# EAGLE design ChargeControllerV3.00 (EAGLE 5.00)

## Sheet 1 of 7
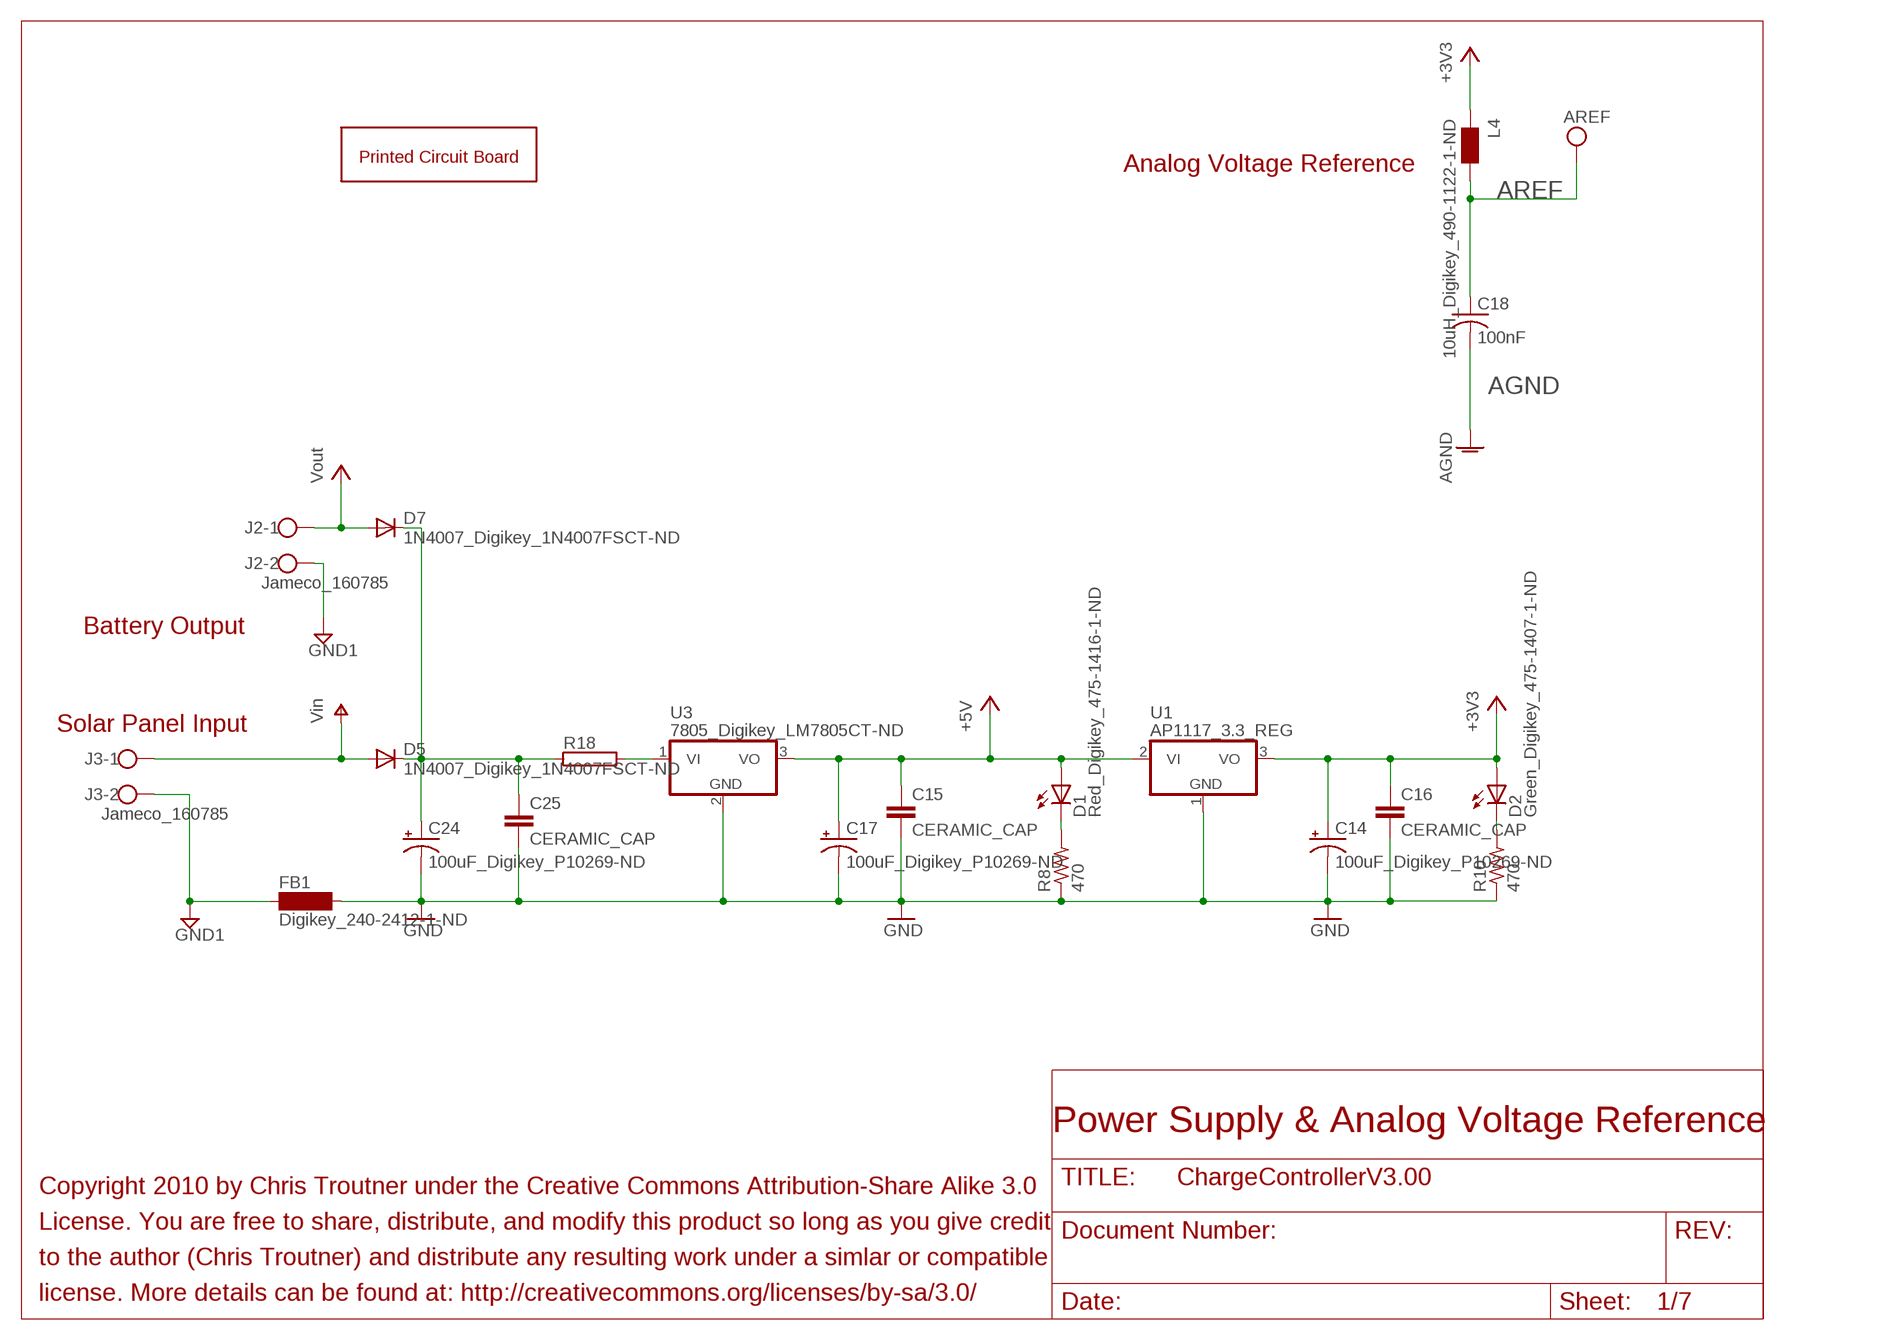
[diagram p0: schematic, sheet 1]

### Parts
C14  100uF_Digikey_P10269-ND  CPOL-USE2.5-7  [E2,5-7]
C15  CERAMIC_CAP  [C1206]
C16  CERAMIC_CAP  [C1206]
C17  100uF_Digikey_P10269-ND  CPOL-USE2.5-7  [E2,5-7]
C18  100nF  C-USC1206K  [C1206K]
C24  100uF_Digikey_P10269-ND  CPOL-USE2.5-7  [E2,5-7]
C25  CERAMIC_CAP  [C1206]
D1  Red_Digikey_475-1416-1-ND  LED_1206  [CHIPLED_1206]
D2  Green_Digikey_475-1407-1-ND  LED_1206  [CHIPLED_1206]
D5  1N4007_Digikey_1N4007FSCT-ND  1N4004  [DO41-10]
D7  1N4007_Digikey_1N4007FSCT-ND  1N4004  [DO41-10]
FB1  Digikey_240-2412-1-ND  SM-1206  [SM-1206]
J2  Jameco_160785  W237-102  [W237-102]
J3  Jameco_160785  W237-102  [W237-102]
L4  10uH_Digikey_490-1122-1-ND  WE-MK_0805  [0805]
R8  470  RESISTOR_1206  [C1206]
R10  470  RESISTOR_1206  [C1206]
R18  RMPC70-2  [MPC70-2]
U1  AP1117_3.3_REG  [TO252]
U3  7805_Digikey_LM7805CT-ND  7805T  [TO220H]
U$1  PCB_RM2015S  [PCB_RM2015S]

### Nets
+3V3: C14.+ C16.1 D2.A L4.1 U1.3(VO) ; also sheet 6
+5V: C15.1 C17.+ D1.A U1.2(VI) U3.3(VO) ; also sheet 2,3,4,5,6
AGND: C18.2 ; also sheet 5
AREF: C18.1 L4.2
GND: C14.- C15.2 C16.2 C17.- C24.- C25.2 FB1.2 R8.1 R10.1 U1.1(GND) U3.2(GND) ; also sheet 2,3,4,5,6
GND1: FB1.1 J2.2 J3.2 ; also sheet 2
N$1: C24.+ C25.1 D5.C D7.C R18.1
N$3: R18.2 U3.1(VI)
N$5: D1.C R8.2
N$6: D2.C R10.2
N$35: D7.A J2.1 ; supply symbol labelled Vout ; also sheet 2,3
VIN: D5.A J3.1 ; supply symbol labelled Vin ; also sheet 2,3

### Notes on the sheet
- Analog Voltage Reference
- Battery Output
- Solar Panel Input
- Power Supply & Analog Voltage Reference
- Copyright 2010 by Chris Troutner under the Creative Commons Attribution-Share Alike 3.0
- License. You are free to share, distribute, and modify this product so long as you give credit
- to the author (Chris Troutner) and distribute any resulting work under a simlar or compatible
- license. More details can be found at: http://creativecommons.org/licenses/by-sa/3.0/

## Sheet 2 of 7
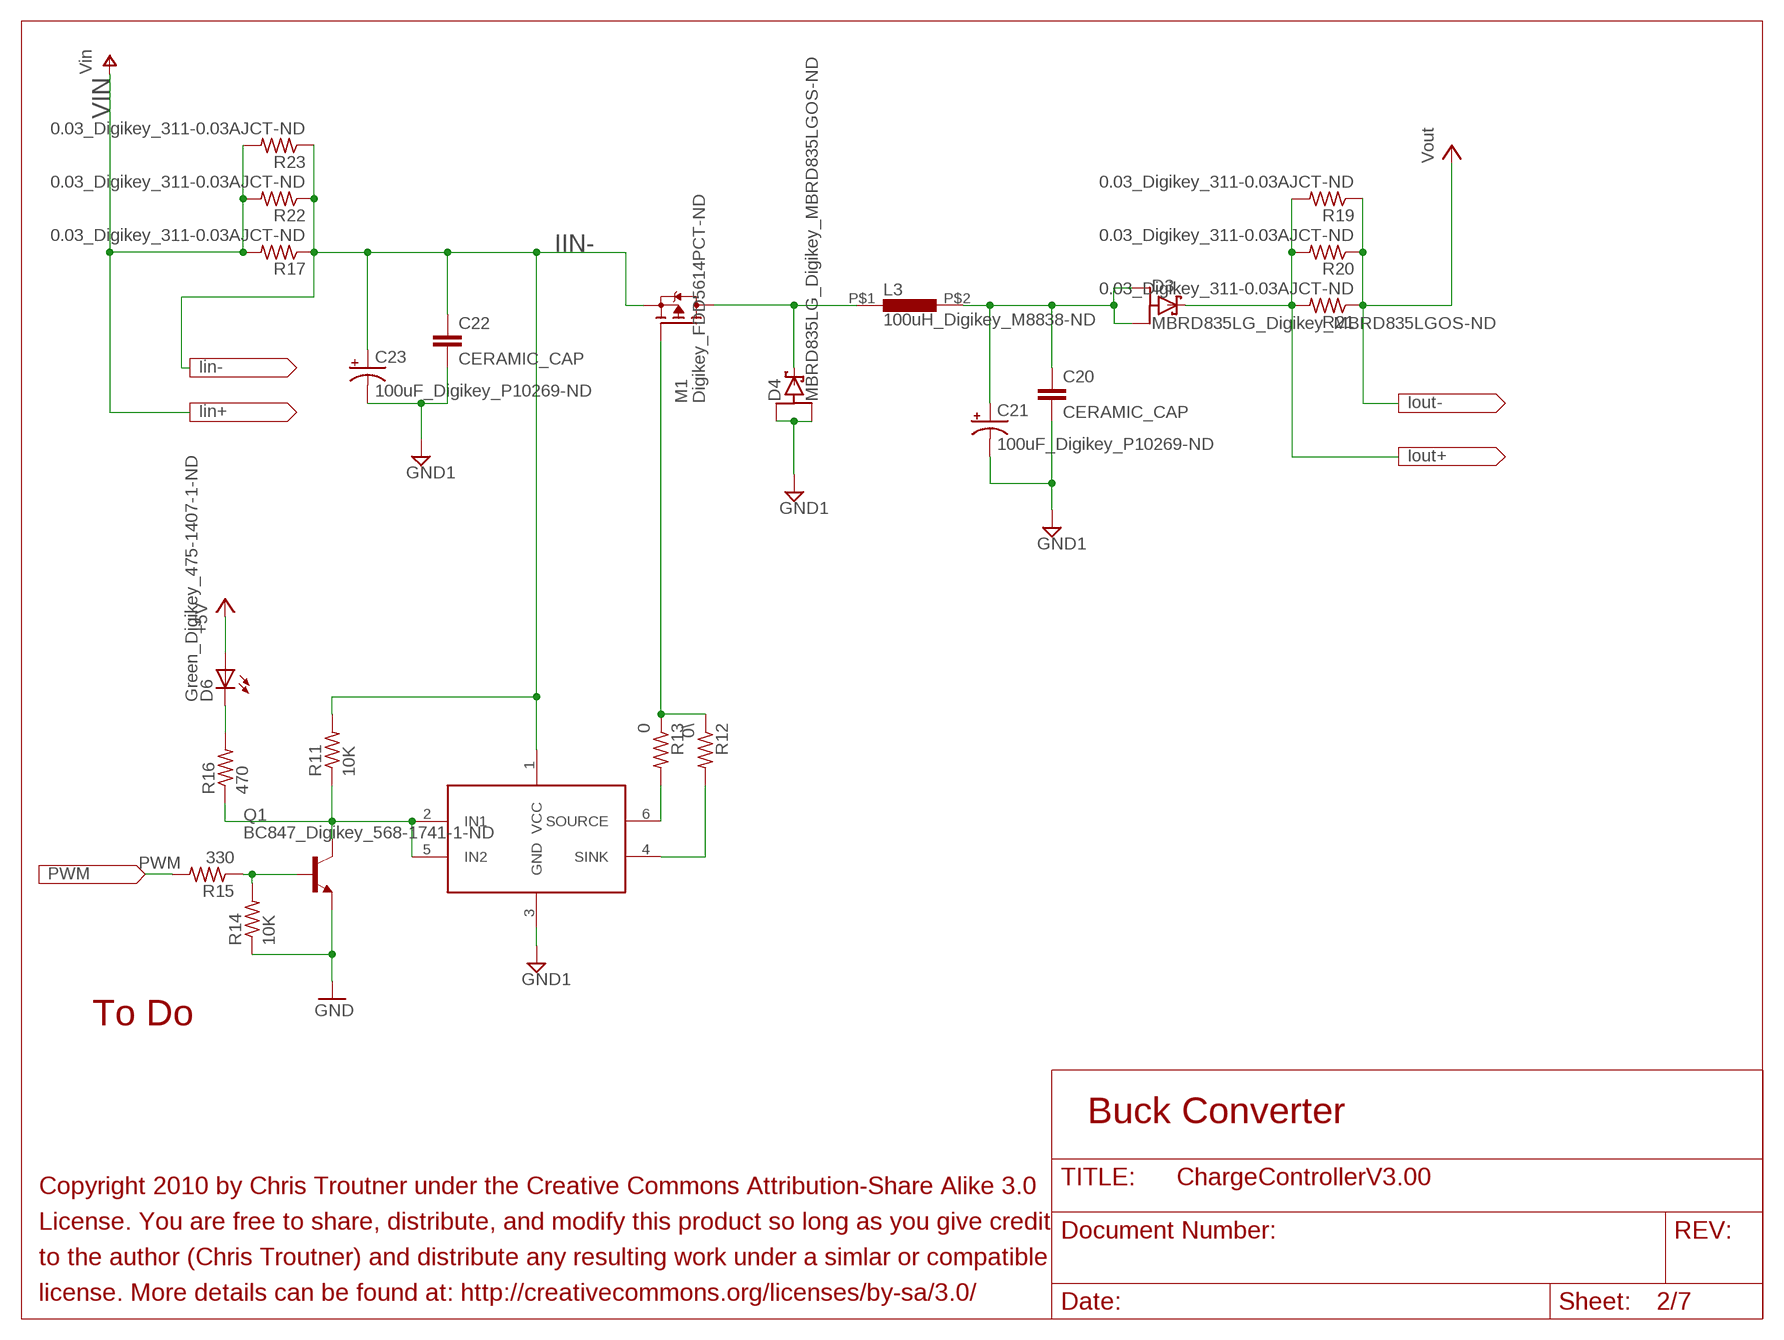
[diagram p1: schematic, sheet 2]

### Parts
C20  CERAMIC_CAP  [C1206]
C21  100uF_Digikey_P10269-ND  CPOL-USE2.5-7  [E2,5-7]
C22  CERAMIC_CAP  [C1206]
C23  100uF_Digikey_P10269-ND  CPOL-USE2.5-7  [E2,5-7]
D3  MBRD835LG_Digikey_MBRD835LGOS-ND  DIODE_SCHOTTKY_MBRD835LG  [DPAK_TO252]
D4  MBRD835LG_Digikey_MBRD835LGOS-ND  DIODE_SCHOTTKY_MBRD835LG  [DPAK_TO252]
D6  Green_Digikey_475-1407-1-ND  LEDCHIPLED_1206  [CHIPLED_1206]
L3  100uH_Digikey_M8838-ND  2312-RC  [2312-RC]
M1  Digikey_FDD5614PCT-ND  SPD30P06PTO252  [TO252]
Q1  BC847_Digikey_568-1741-1-ND  BC849SMD  [SOT23-BEC]
R11  10K  RESISTOR_1206  [C1206]
R12  0\  RESISTOR_1206  [C1206]
R13  0  RESISTOR_1206  [C1206]
R14  10K  RESISTOR_1206  [C1206]
R15  330  RESISTOR_1206  [C1206]
R16  470  RESISTOR_1206  [C1206]
R17  0.03_Digikey_311-0.03AJCT-ND  RESISTOR_1206  [C1206]
R19  0.03_Digikey_311-0.03AJCT-ND  RESISTOR_1206  [C1206]
R20  0.03_Digikey_311-0.03AJCT-ND  RESISTOR_1206  [C1206]
R21  0.03_Digikey_311-0.03AJCT-ND  RESISTOR_1206  [C1206]
R22  0.03_Digikey_311-0.03AJCT-ND  RESISTOR_1206  [C1206]
R23  0.03_Digikey_311-0.03AJCT-ND  RESISTOR_1206  [C1206]
U2  ZXGD3003  [SOT23-6]

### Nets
+5V: D6.A ; also sheet 1,3,4,5,6
GND: Q1.E R14.1 ; also sheet 1,3,4,5,6
GND1: C20.2 C21.- C22.2 C23.- D4.1(A) D4.3(A1) U2.3(GND) ; also sheet 1
IIN-: C22.1 C23.+ M1.2(S) R11.2 R17.1 R22.1 R23.1 U2.1(VCC) ; also sheet 3
IOUT+: D3.4(C) R19.2 R20.2 R21.2 ; also sheet 3
N$8: R13.2 U2.6(SOURCE)
N$9: D6.C R16.2
N$10: Q1.B R14.2 R15.1
N$16: R12.2 U2.4(SINK)
N$21: M1.1(G) R12.1 R13.1
N$24: Q1.C R11.1 R16.1 U2.2(IN1) U2.5(IN2)
N$30: D4.4(C) L3.P$1 M1.3(D)
N$34: C20.1 C21.+ D3.1(A) D3.3(A1) L3.P$2
N$35: R19.1 R20.1 R21.1 ; supply symbol labelled Vout ; also sheet 1,3
PWM: R15.2 ; also sheet 5
VIN: R17.2 R22.2 R23.2 ; supply symbol labelled Vin ; also sheet 1,3

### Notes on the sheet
- To Do
- Buck Converter
- Copyright 2010 by Chris Troutner under the Creative Commons Attribution-Share Alike 3.0
- License. You are free to share, distribute, and modify this product so long as you give credit
- to the author (Chris Troutner) and distribute any resulting work under a simlar or compatible
- license. More details can be found at: http://creativecommons.org/licenses/by-sa/3.0/

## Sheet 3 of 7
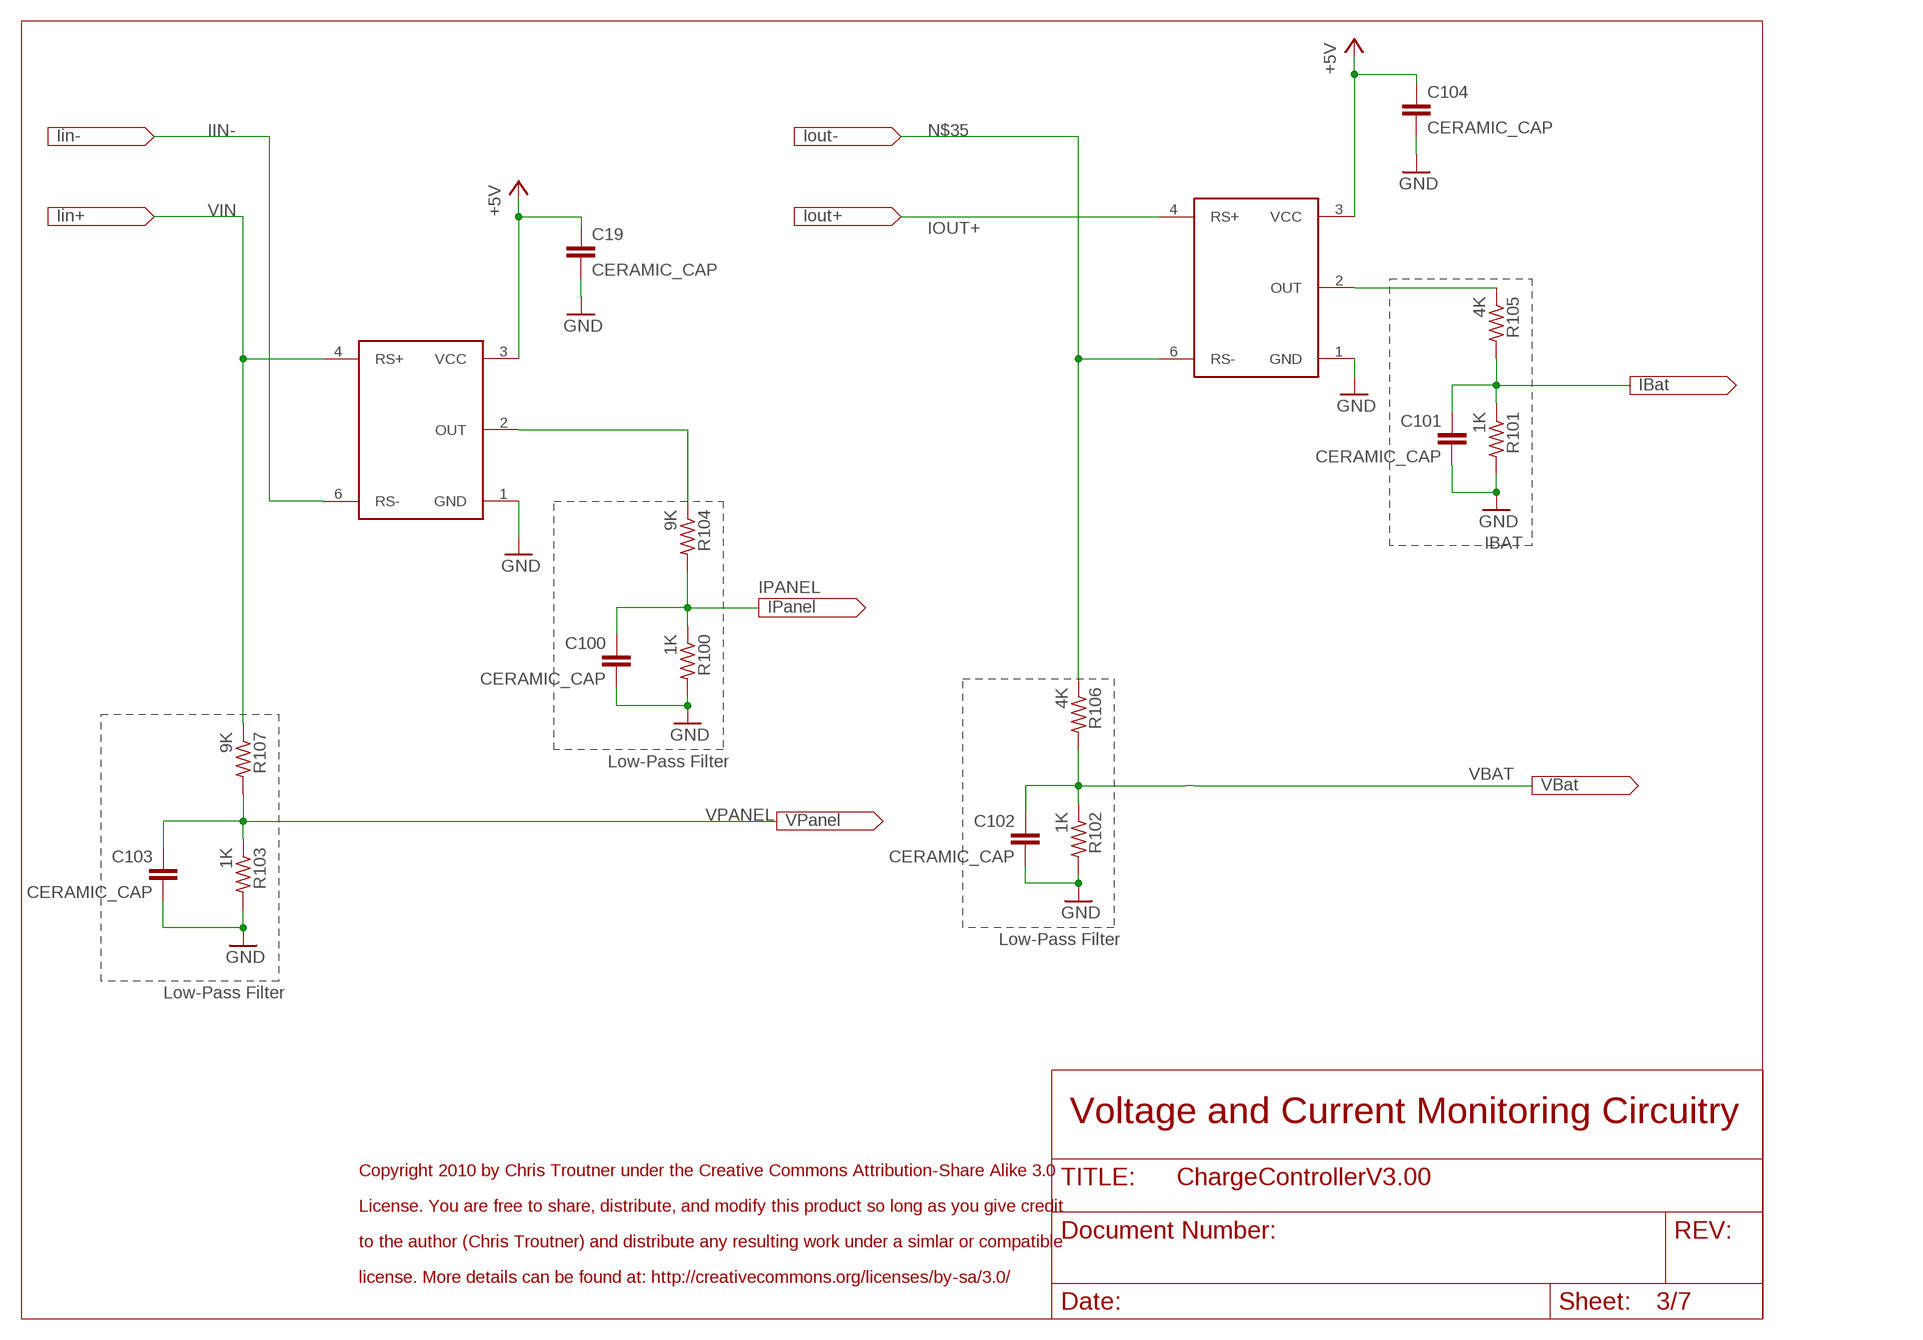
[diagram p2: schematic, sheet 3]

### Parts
C19  CERAMIC_CAP  [C1206]
C100  CERAMIC_CAP  [C1206]
C101  CERAMIC_CAP  [C1206]
C102  CERAMIC_CAP  [C1206]
C103  CERAMIC_CAP  [C1206]
C104  CERAMIC_CAP  [C1206]
IC3  MAX4372_CURRENT  [SOT23-6]
IC4  MAX4372_CURRENT  [SOT23-6]
R100  1K  RESISTOR_1206  [C1206]
R101  1K  RESISTOR_1206  [C1206]
R102  1K  RESISTOR_1206  [C1206]
R103  1K  RESISTOR_1206  [C1206]
R104  9K  RESISTOR_1206  [C1206]
R105  4K  RESISTOR_1206  [C1206]
R106  4K  RESISTOR_1206  [C1206]
R107  9K  RESISTOR_1206  [C1206]

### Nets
+5V: C19.1 C104.1 IC3.3(VCC) IC4.3(VCC) ; also sheet 1,2,4,5,6
GND: C19.2 C100.2 C101.2 C102.2 C103.2 C104.2 IC3.1(GND) IC4.1(GND) R100.2 R101.2 R102.2 R103.2 ; also sheet 1,2,4,5,6
IBAT: C101.1 R101.1 R105.2 ; also sheet 5
IIN-: IC3.6(RS-) ; also sheet 2
IOUT+: IC4.4(RS+) ; also sheet 2
IPANEL: C100.1 R100.1 R104.2 ; also sheet 5
N$12: IC4.2(OUT) R105.1
N$14: IC3.2(OUT) R104.1
N$35: IC4.6(RS-) R106.1 ; also sheet 1,2
VBAT: C102.1 R102.1 R106.2 ; also sheet 5
VIN: IC3.4(RS+) R107.1 ; also sheet 1,2
VPANEL: C103.1 R103.1 R107.2 ; also sheet 5

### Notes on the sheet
- Low-Pass Filter
- Low-Pass Filter
- Low-Pass Filter
- Voltage and Current Monitoring Circuitry
- Copyright 2010 by Chris Troutner under the Creative Commons Attribution-Share Alike 3.0
- License. You are free to share, distribute, and modify this product so long as you give credit
- to the author (Chris Troutner) and distribute any resulting work under a simlar or compatible
- license. More details can be found at: http://creativecommons.org/licenses/by-sa/3.0/

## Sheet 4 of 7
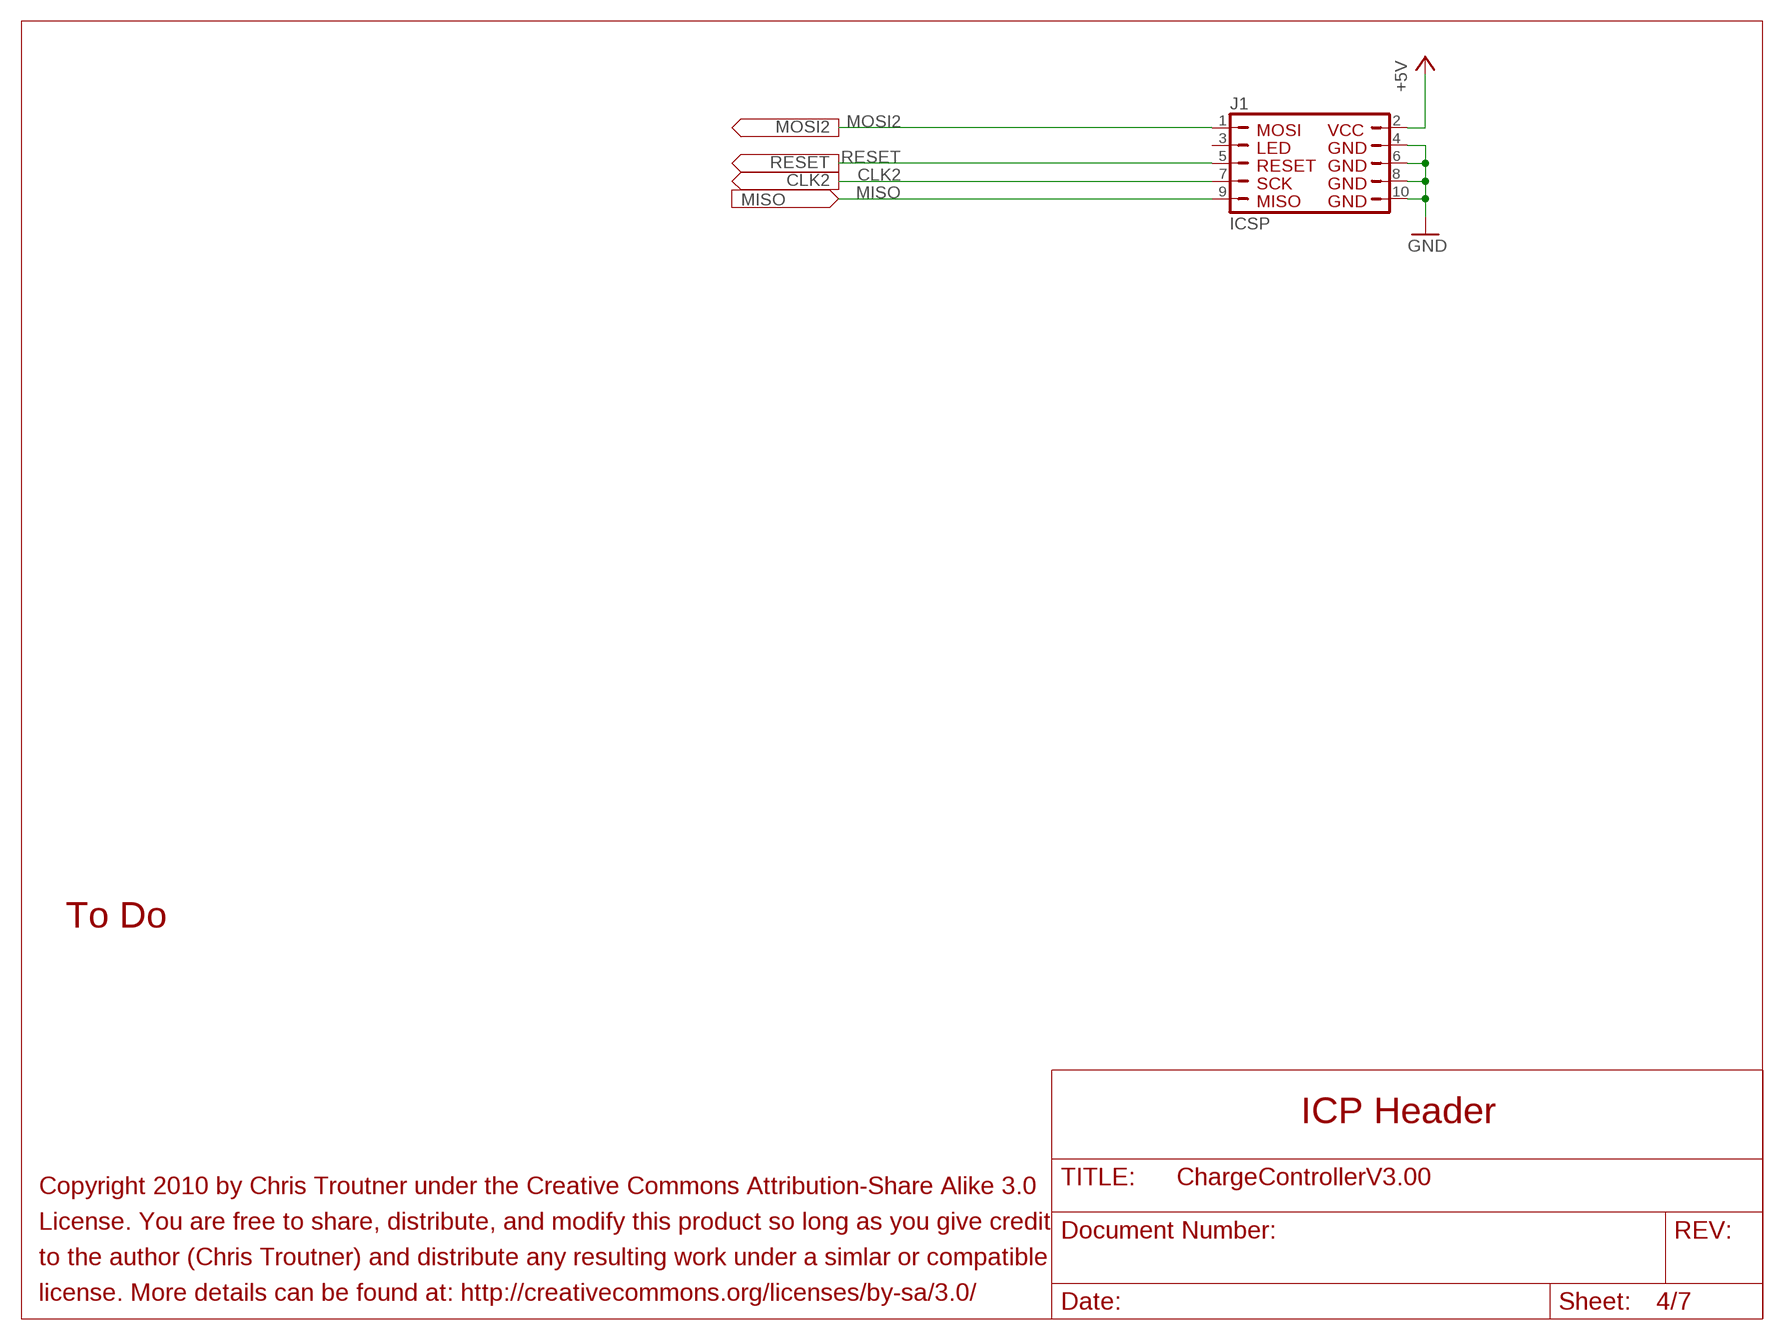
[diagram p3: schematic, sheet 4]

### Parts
J1  ICSP  [ICSP]

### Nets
+5V: J1.2 ; also sheet 1,2,3,5,6
CLK2: J1.7 ; also sheet 5,6
GND: J1.4 J1.6 J1.8 J1.10 ; also sheet 1,2,3,5,6
MISO: J1.9 ; also sheet 5,6
MOSI2: J1.1 ; also sheet 5,6
RESET: J1.5 ; also sheet 5
Unconnected: J1.3

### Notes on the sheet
- To Do
- ICP Header
- Copyright 2010 by Chris Troutner under the Creative Commons Attribution-Share Alike 3.0
- License. You are free to share, distribute, and modify this product so long as you give credit
- to the author (Chris Troutner) and distribute any resulting work under a simlar or compatible
- license. More details can be found at: http://creativecommons.org/licenses/by-sa/3.0/

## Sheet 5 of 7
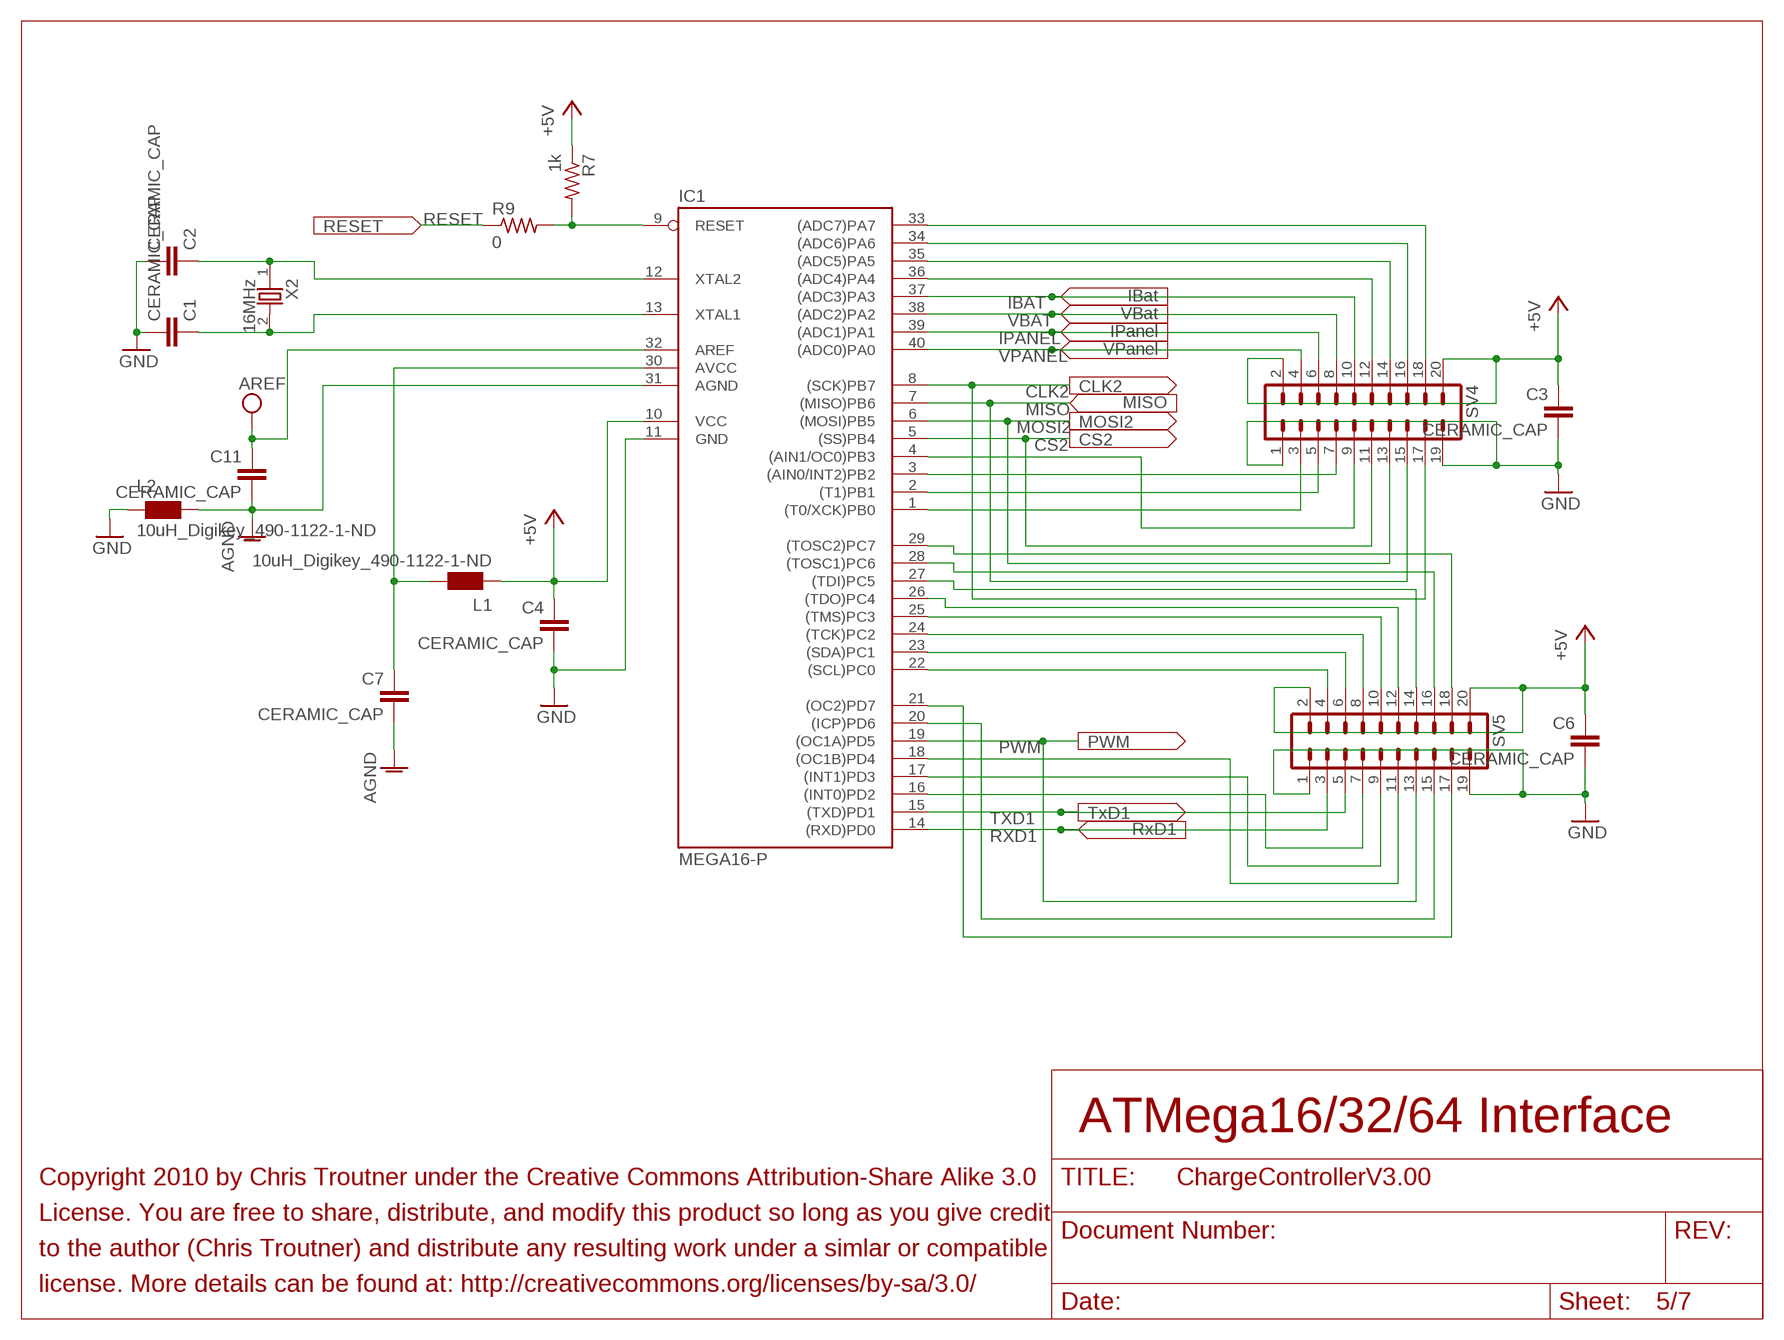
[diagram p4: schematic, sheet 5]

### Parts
C1  CERAMIC_CAP  [C1206]
C2  CERAMIC_CAP  [C1206]
C3  CERAMIC_CAP  [C1206]
C4  CERAMIC_CAP  [C1206]
C6  CERAMIC_CAP  [C1206]
C7  CERAMIC_CAP  [C1206]
C11  CERAMIC_CAP  [C1206]
IC1  MEGA16-P  [DIL40]
L1  10uH_Digikey_490-1122-1-ND  WE-MK_0805  [0805]
L2  10uH_Digikey_490-1122-1-ND  WE-MK_0805  [0805]
R7  1k  RESISTOR_1206  [C1206]
R9  0  RESISTOR_1206  [C1206]
SV4  MA10-2  [MA10-2]
SV5  MA10-2  [MA10-2]
X2  16MHz  20MHZ_XTL  [HS49S]

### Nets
+5V: C3.1 C4.1 C6.1 IC1.10(VCC) L1.1 R7.1 SV4.2 SV4.20 SV5.2 SV5.20 ; also sheet 1,2,3,4,6
AGND: C7.2 C11.2 IC1.31(AGND) L2.2 ; also sheet 1
CLK2: IC1.8((SCK)PB7) SV4.17 ; also sheet 4,6
CS2: IC1.5((SS)PB4) SV4.11 ; also sheet 6
GND: C1.2 C2.2 C3.2 C4.2 C6.2 IC1.11(GND) L2.1 SV4.1 SV4.19 SV5.1 SV5.19 ; also sheet 1,2,3,4,6
IBAT: IC1.37((ADC3)PA3) SV4.10 ; also sheet 3
IPANEL: IC1.39((ADC1)PA1) SV4.6 ; also sheet 3
MISO: IC1.7((MISO)PB6) SV4.15 ; also sheet 4,6
MOSI2: IC1.6((MOSI)PB5) SV4.13 ; also sheet 4,6
N$7: C7.1 IC1.30(AVCC) L1.2
N$15: C2.1 IC1.12(XTAL2) X2.1
N$17: C1.1 IC1.13(XTAL1) X2.2
N$18: IC1.9(RESET) R7.2 R9.2
N$19: IC1.33((ADC7)PA7) SV4.18
N$20: IC1.34((ADC6)PA6) SV4.16
N$22: IC1.35((ADC5)PA5) SV4.14
N$23: IC1.36((ADC4)PA4) SV4.12
N$27: IC1.1((T0/XCK)PB0) SV4.3
N$62: IC1.2((T1)PB1) SV4.5
N$67: IC1.3((AIN0/INT2)PB2) SV4.7
N$68: IC1.4((AIN1/OC0)PB3) SV4.9
N$69: IC1.16((INT0)PD2) SV5.7
N$70: IC1.17((INT1)PD3) SV5.9
N$71: IC1.22((SCL)PC0) SV5.4
N$72: IC1.23((SDA)PC1) SV5.6
N$73: IC1.24((TCK)PC2) SV5.8
N$74: IC1.25((TMS)PC3) SV5.10
N$75: IC1.26((TDO)PC4) SV5.12
N$76: IC1.27((TDI)PC5) SV5.14
N$77: IC1.28((TOSC1)PC6) SV5.16
N$78: IC1.29((TOSC2)PC7) SV5.18
N$79: IC1.18((OC1B)PD4) SV5.11
N$80: IC1.20((ICP)PD6) SV5.15
N$81: IC1.21((OC2)PD7) SV5.17
PWM: IC1.19((OC1A)PD5) SV5.13 ; also sheet 2
RESET: R9.1 ; also sheet 4
RXD1: IC1.14((RXD)PD0) SV5.3 ; also sheet 6
TXD1: IC1.15((TXD)PD1) SV5.5 ; also sheet 6
VBAT: IC1.38((ADC2)PA2) SV4.8 ; also sheet 3
VDD: C11.1 IC1.32(AREF) ; supply symbol labelled AREF
VPANEL: IC1.40((ADC0)PA0) SV4.4 ; also sheet 3

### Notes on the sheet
- ATMega16/32/64 Interface
- Copyright 2010 by Chris Troutner under the Creative Commons Attribution-Share Alike 3.0
- License. You are free to share, distribute, and modify this product so long as you give credit
- to the author (Chris Troutner) and distribute any resulting work under a simlar or compatible
- license. More details can be found at: http://creativecommons.org/licenses/by-sa/3.0/

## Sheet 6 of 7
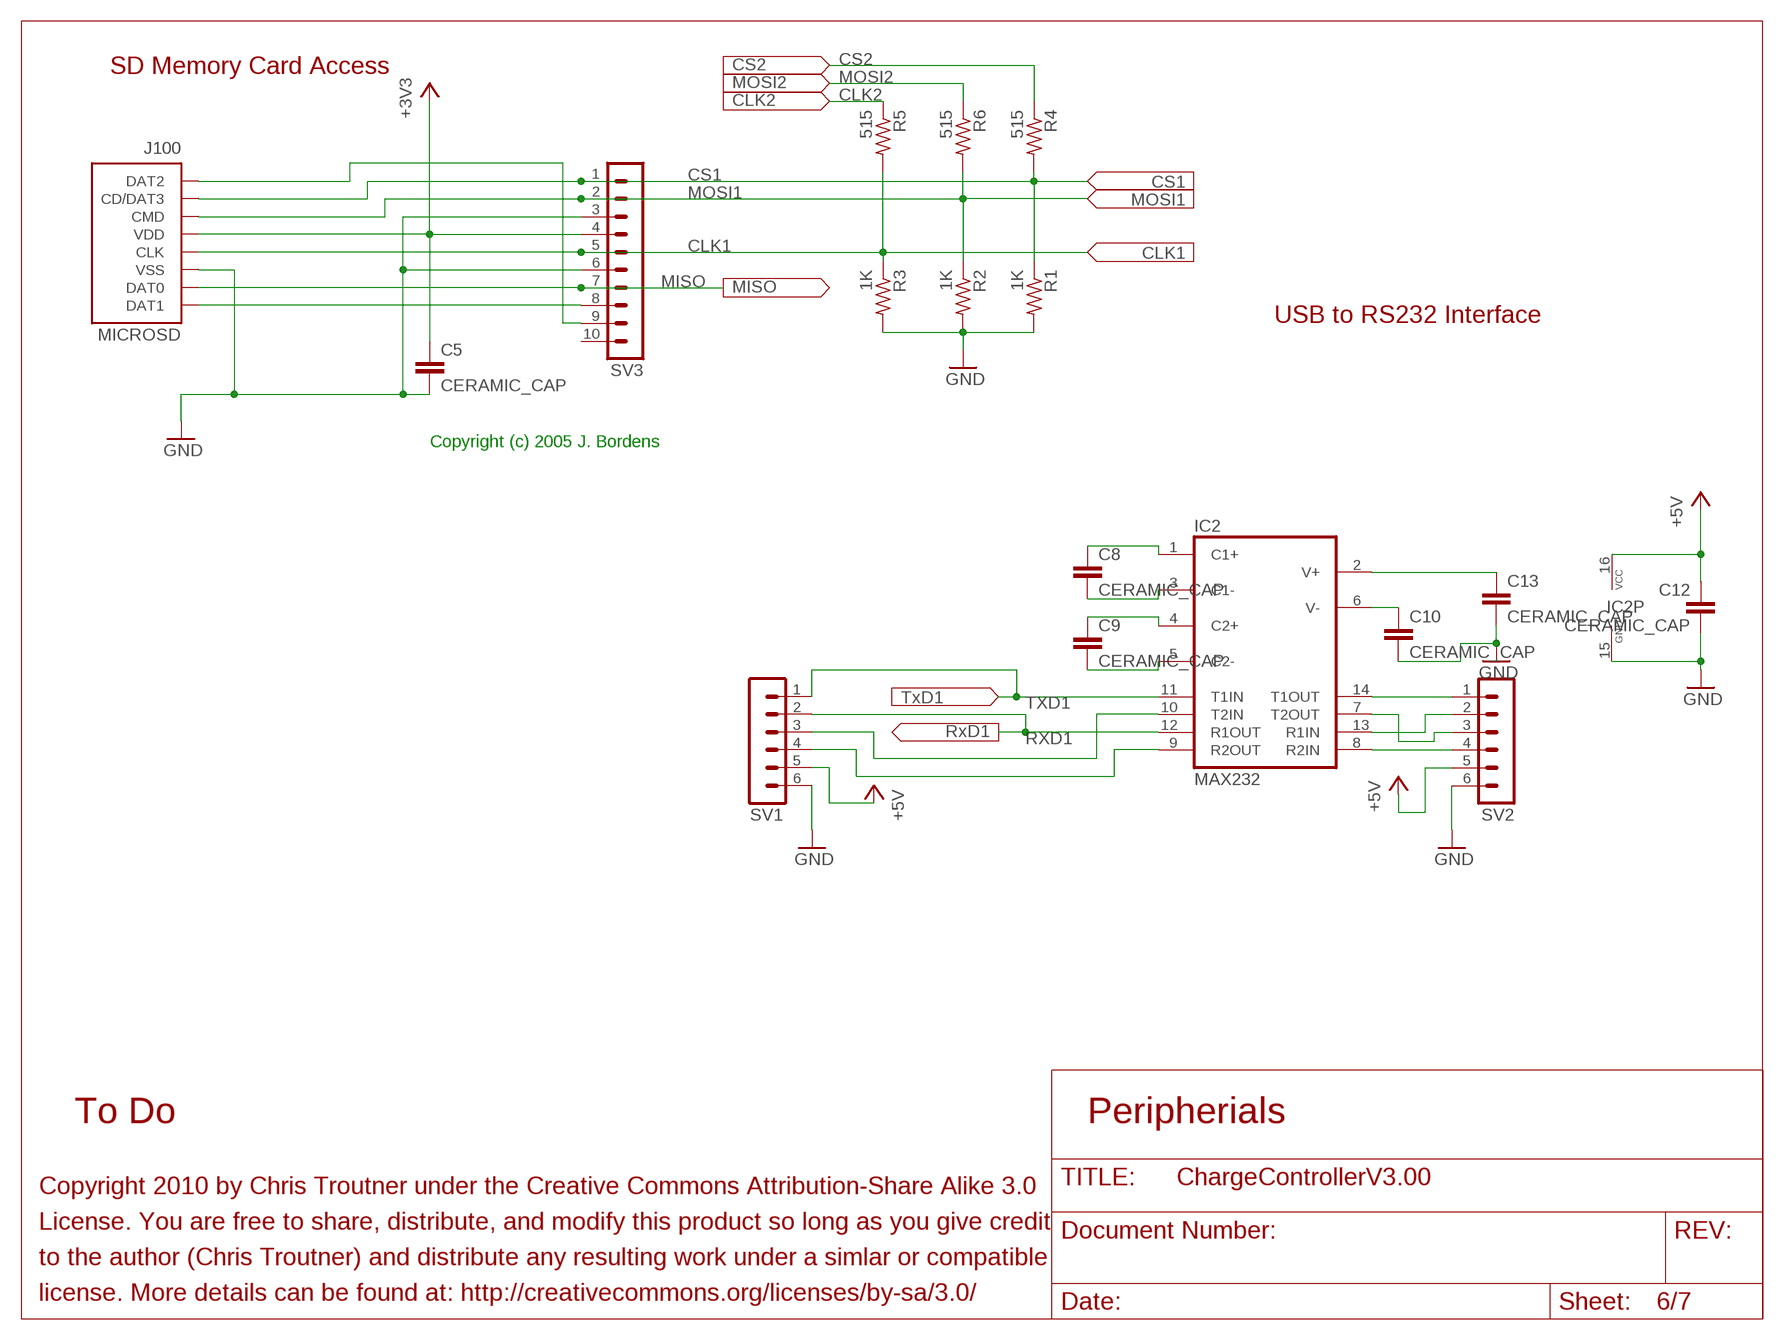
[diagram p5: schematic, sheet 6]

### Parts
C5  CERAMIC_CAP  [C1206]
C8  CERAMIC_CAP  [C1206]
C9  CERAMIC_CAP  [C1206]
C10  CERAMIC_CAP  [C1206]
C12  CERAMIC_CAP  [C1206]
C13  CERAMIC_CAP  [C1206]
IC2  MAX232  [DIL16]
J100  MICROSD  [DM3D_SD_MEMORY]
R1  1K  RESISTOR_1206  [C1206]
R2  1K  RESISTOR_1206  [C1206]
R3  1K  RESISTOR_1206  [C1206]
R4  515  RESISTOR_1206  [C1206]
R5  515  RESISTOR_1206  [C1206]
R6  515  RESISTOR_1206  [C1206]
SV1  MA06-1  [MA06-1]
SV2  MA06-1  [MA06-1]
SV3  MA10-1  [MA10-1]

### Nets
+3V3: C5.1 J100.P$5(VDD) SV3.4 ; also sheet 1
+5V: C12.1 IC2.16(VCC) SV1.5 SV2.5 ; also sheet 1,2,3,4,5
CLK1: J100.P$4(CLK) R3.1 R5.2 SV3.5
CLK2: R5.1 ; also sheet 4,5
CS1: J100.P$7(CD/DAT3) R1.1 R4.2 SV3.1
CS2: R4.1 ; also sheet 5
GND: C5.2 C10.2 C12.2 C13.2 IC2.15(GND) J100.P$3(VSS) R1.2 R2.2 R3.2 SV1.6 SV2.6 SV3.3 SV3.6 ; also sheet 1,2,3,4,5
MISO: J100.P$2(DAT0) SV3.7 ; also sheet 4,5
MOSI1: J100.P$6(CMD) R2.1 R6.2 SV3.2
MOSI2: R6.1 ; also sheet 4,5
N$2: C9.1 IC2.4(C2+)
N$4: C9.2 IC2.5(C2-)
N$11: C8.2 IC2.3(C1-)
N$13: C8.1 IC2.1(C1+)
N$26: J100.P$8(DAT2) SV3.9
N$28: C10.1 IC2.6(V-)
N$29: J100.P$1(DAT1) SV3.8
N$31: C13.1 IC2.2(V+)
N$32: IC2.10(T2IN) SV1.3
N$33: IC2.9(R2OUT) SV1.4
N$36: IC2.14(T1OUT) SV2.1
N$37: IC2.13(R1IN) SV2.2
N$38: IC2.7(T2OUT) SV2.3
N$39: IC2.8(R2IN) SV2.4
RXD1: IC2.12(R1OUT) SV1.2 ; also sheet 5
TXD1: IC2.11(T1IN) SV1.1 ; also sheet 5
Unconnected: SV3.10

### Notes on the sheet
- SD Memory Card Access
- USB to RS232 Interface
- Copyright (c) 2005 J. Bordens
- To Do | Peripherials
- Copyright 2010 by Chris Troutner under the Creative Commons Attribution-Share Alike 3.0
- License. You are free to share, distribute, and modify this product so long as you give credit
- to the author (Chris Troutner) and distribute any resulting work under a simlar or compatible
- license. More details can be found at: http://creativecommons.org/licenses/by-sa/3.0/

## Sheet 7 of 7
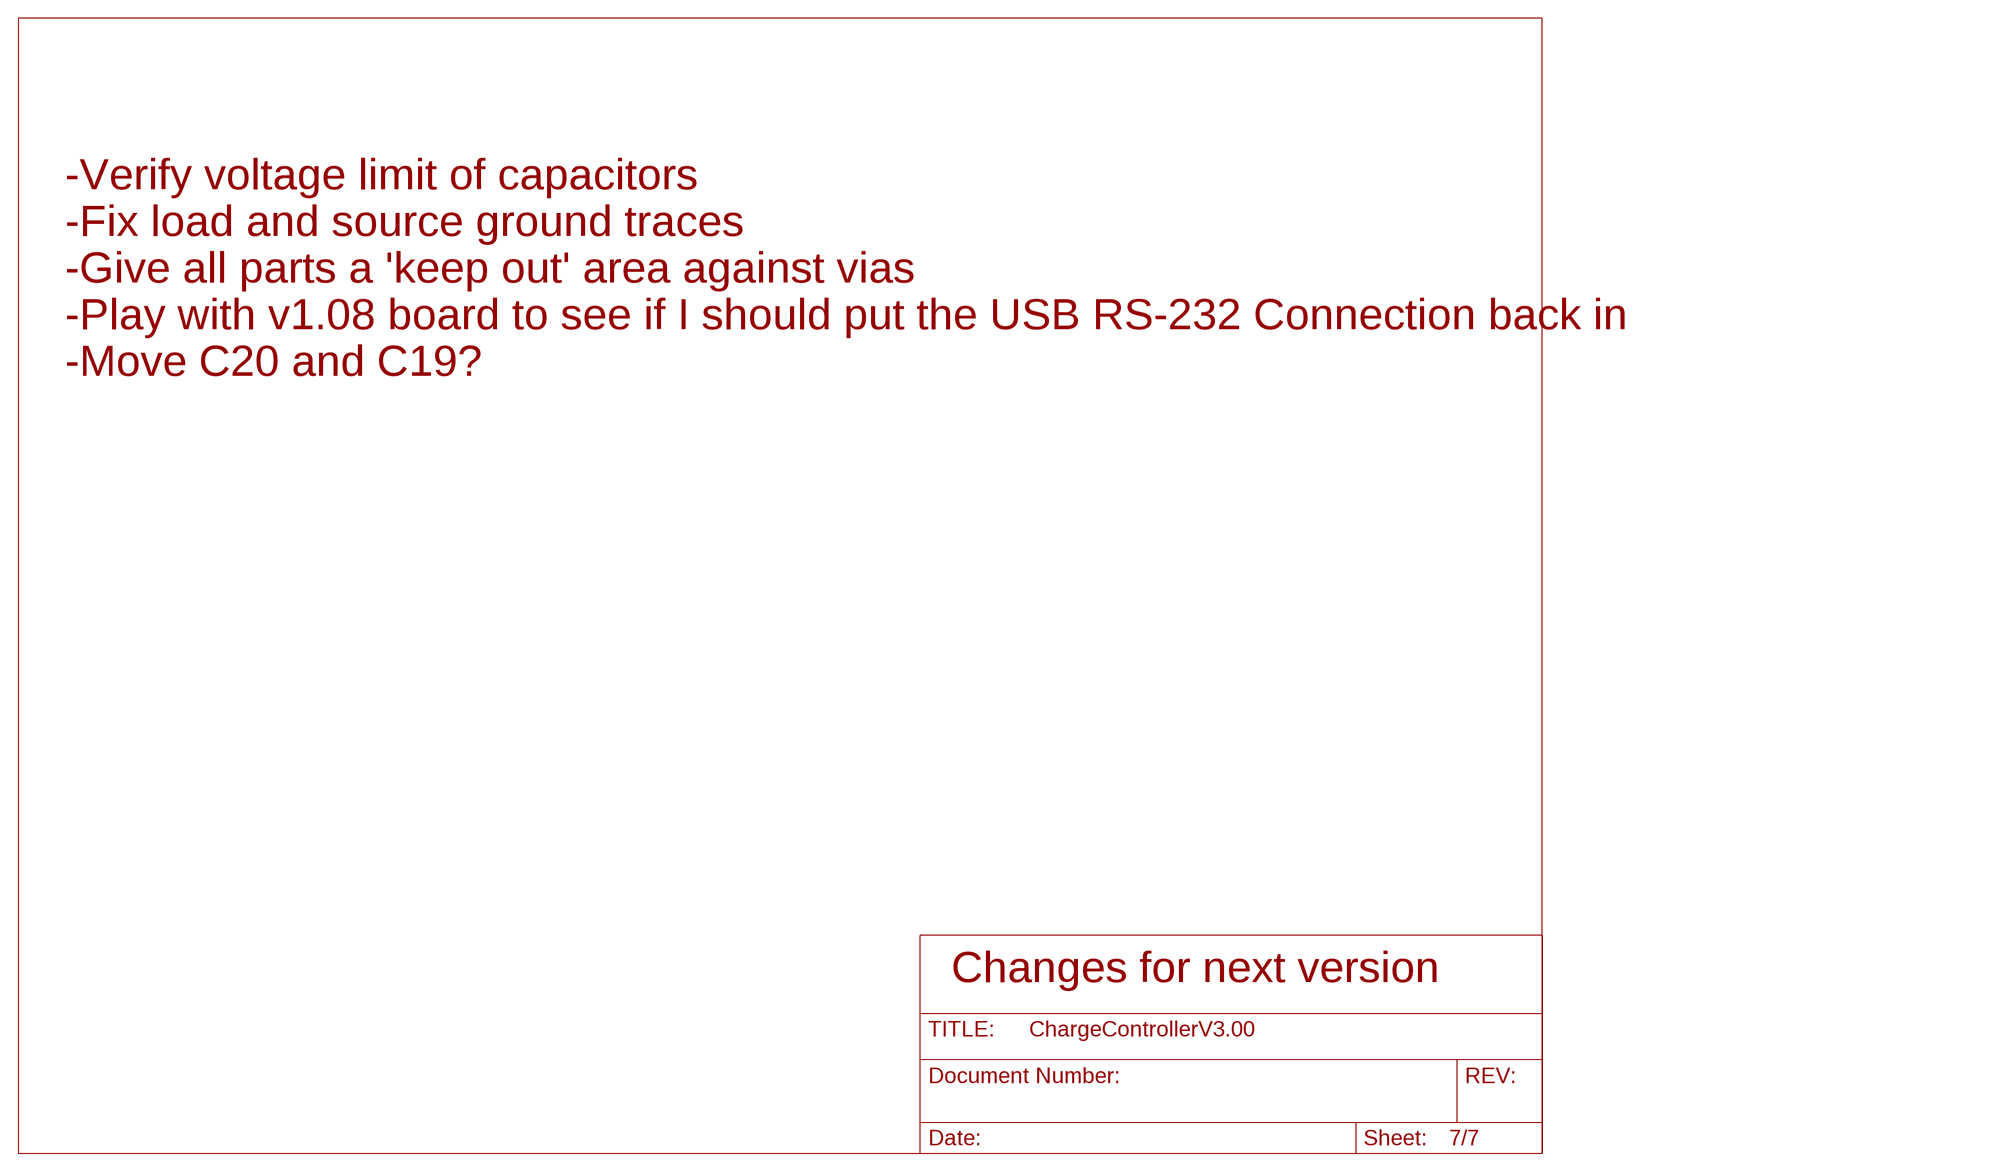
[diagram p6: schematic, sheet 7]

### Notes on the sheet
- -Verify voltage limit of capacitors
- -Fix load and source ground traces
- -Give all parts a 'keep out' area against vias
- -Play with v1.08 board to see if I should put the USB RS-232 Connection back in
- -Move C20 and C19?
- Changes for next version

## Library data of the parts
C1-C13 C15 C16 C19 C20 C22 C25 C100-C104 = ChargeController:CERAMIC_CAP: Ceramic cap in a 1206 SMT package
C14 C17 C21 C23 C24 = rcl:CPOL-US: POLARIZED CAPACITOR, American symbol
C18 = rcl:C-US: CAPACITOR, American symbol
D1 D2 = ChargeController:LED_1206: Chip LED in a 1206 package.
D3 D4 = EV:DIODE_SCHOTTKY_MBRD835LG: Schottkey diode from ON Semiconductor part # MBRD835LG. Digikey # MBRD835LGOS-ND
D5 D7 = diode:1N4004: DIODE
D6 = led:LED: LED
FB1 = inductor-neosid:SM-1206: INDUCTOR
IC1 = atmel:MEGA16-P: MICROCONTROLLER 16 Kbytes FLASH 1 kbytes SRAM 512 bytes EEPROM USART 8-channel 10 bit ADC Source: avr.lbr
IC2 = maxim:MAX232: RS232 TRANSEIVER
IC3 IC4 = ChargeController:MAX4372_CURRENT: MAX4372 Current Sense Amplifier
J1 = EV:ICSP: ICSP header for programming AVR microcontrollers
J2 J3 = con-wago-500:W237-102: WAGO SCREW CLAMP
J100 = ChargeController:MICROSD: MicroSD Card Interface. DM3D-SF from Hirose. Digikey # HR1941CT-ND
L1 L2 L4 = wuerth-elektronik:WE-MK: SMD Multilayer Ceramic Inductors WE-MK
L3 = EV:2312-RC: Bourns 2312-H-RC. Digikey # M8838-ND. 100uH 7amps toroid
M1 = transistor-fet:SPD30P06P: SIPMOS(R) Power-Transistor P-Channel, Enhancement mode Source: http://www.infineon.com/upload/Document/cmc_upload/documents/012/3615/SPD_U30P06P.pdf
Q1 = transistor-npn:BC849*: NPN Transistor
R1-R17 R19-R23 R100-R107 = ChargeController:RESISTOR_1206: Resistor in 1206 Package
R18 = resistor-power:R: Power Resitor
SV1 SV2 = con-lstb:MA06-1: PIN HEADER
SV3 = con-lstb:MA10-1: PIN HEADER
SV4 SV5 = con-lstb:MA10-2: PIN HEADER
U1 = ChargeController:AP1117_3.3_REG: AP1117 3.3V Regulator. Digikey # AP1117D33GCT-ND
U2 = EV:ZXGD3003
U3 = linear:78*: Positive VOLTAGE REGULATOR Source: http://cache.national.com/ds/LM/LM78L05.pdf http://www.fairchildsemi.com/ds/LM/LM7805.pdf
U$1 = EV:PCB_RM2015S: Hammond Manufacturing RM2015S Project Box
X2 = EV:20MHZ_XTL

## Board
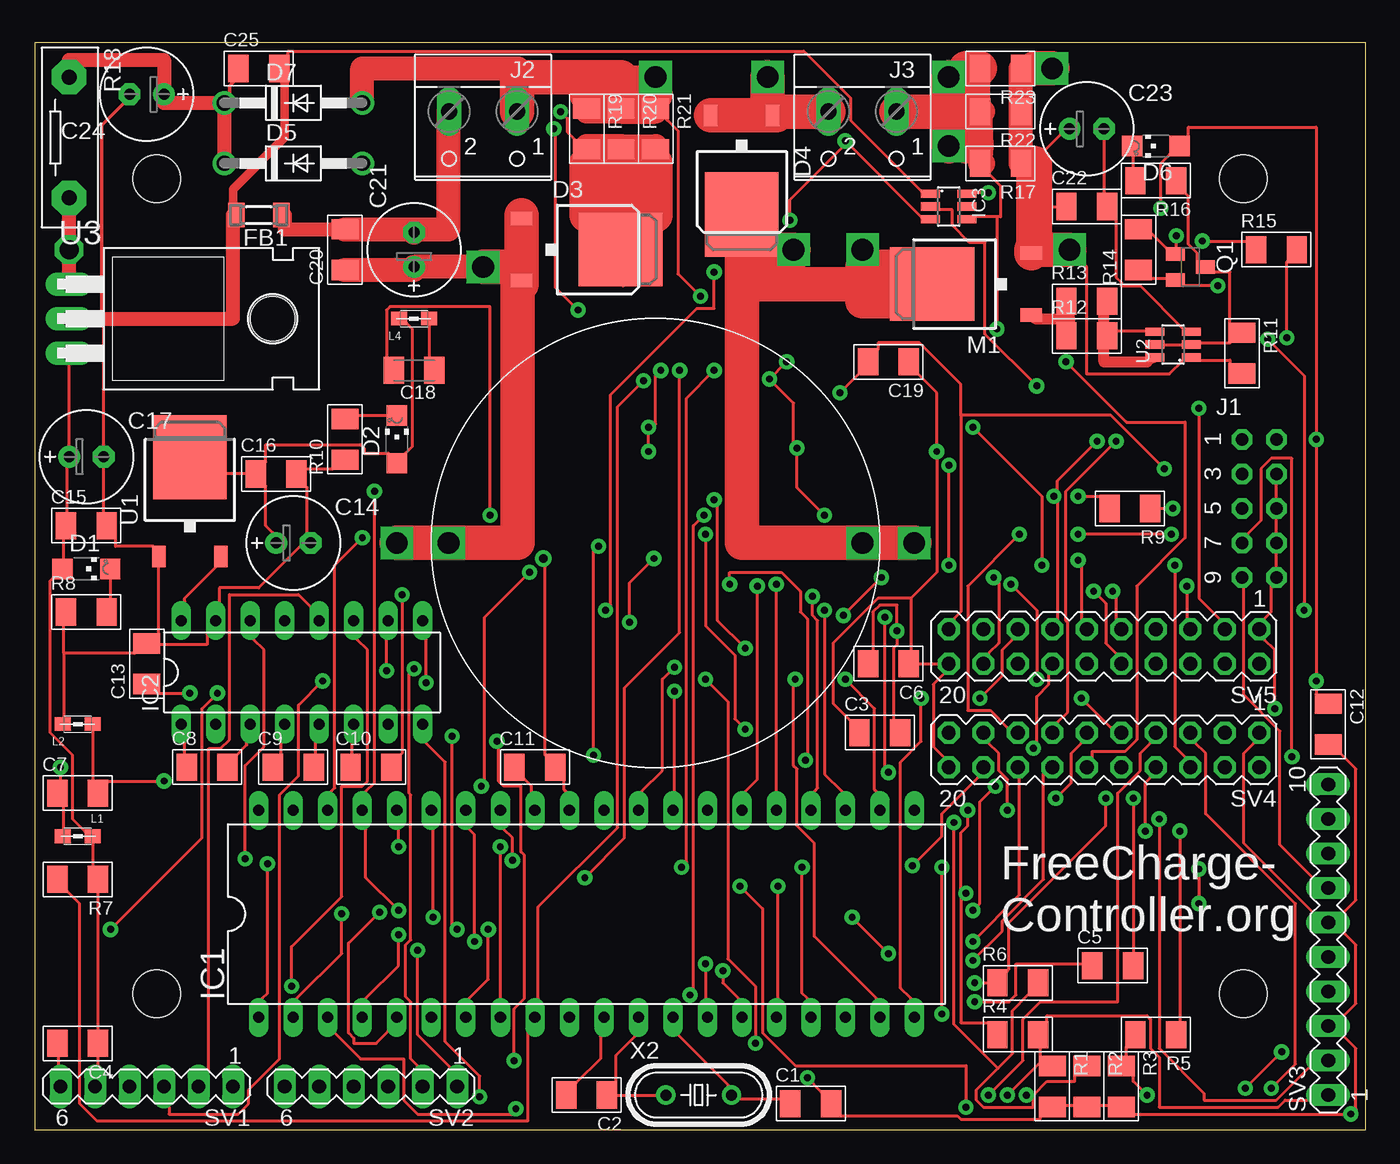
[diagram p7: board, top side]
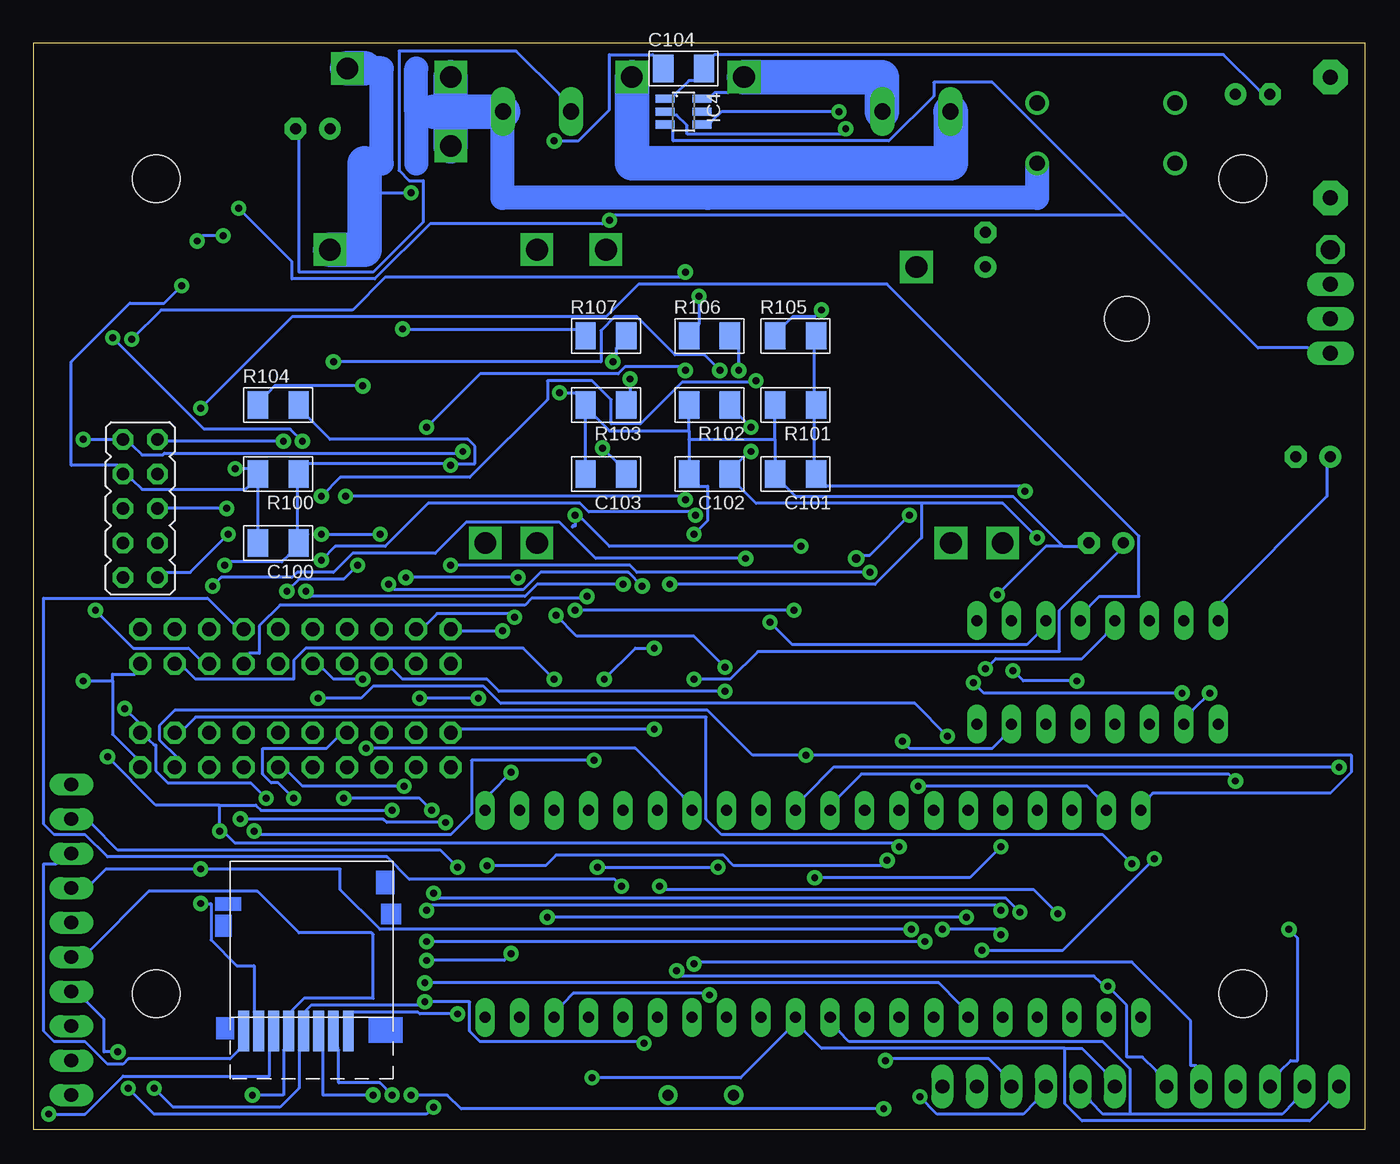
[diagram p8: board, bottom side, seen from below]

Size 98 x 80 mm. Coordinates in mm from the lower left corner, seen from the top.
Copper layers (1*16): Top 0.035mm / dielectric 1.5mm / Bottom 0.035mm
Design rules "default *": minimum track width 8mil, minimum drill 20mil, track to track 8mil, track to pad 8mil, pad to pad 8mil, via to via 8mil, smd to smd 0mil, copper to edge 20mil, drill to drill 24mil, minimum pad ring 12mil, minimum via ring 12mil, stop-mask expansion 4mil, vias tented up to drill 0mil, thermal gap 10mil
tKeepout: area 5.1,66 to 12.7,73.7; area 85.1,66 to 92.7,73.7; area 85.1,6.3 to 92.7,14; area 5.1,6.3 to 12.7,14
bKeepout: area 5.1,6.3 to 12.7,14; area 85.1,6.3 to 92.7,14; area 85.1,66 to 92.7,73.7; area 5.1,66 to 12.7,73.7
tRestrict: area 5.1,6.3 to 12.7,14; area 85.1,6.3 to 92.7,14; area 85.1,66 to 92.7,73.7; area 5.1,66 to 12.7,73.7
bRestrict: area 5.1,6.3 to 12.7,14; area 85.1,6.3 to 92.7,14; area 85.1,66 to 92.7,73.7; area 5.1,66 to 12.7,73.7

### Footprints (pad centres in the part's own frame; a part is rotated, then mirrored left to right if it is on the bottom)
C1206 = smd 1.5 x 2: 1 -1.5,0; 2 1.5,0
E2,5-7 = drill 0.813 pad 1.6 round: + -1.27,0 | drill 0.813 pad 1.6 octagon: - 1.27,0
C1206K = smd 1.5 x 2: 1 -1.5,0; 2 1.5,0
CHIPLED_1206 = smd 1.5 x 1.5: A 0,-1.75; C 0,1.75
DPAK_TO252 = smd 1 x 1.6: 1 -2.28,-6.07; 3 2.28,-6.07 | smd 5.4 x 6.2: 4 0,1.23
DO41-10 = drill 1.118 round: A 5.08,0; C -5.08,0
SM-1206 = smd 1.2 x 1.8: 1 -1.65,0; 2 1.65,0
DIL40 = drill 0.813 long: 1 -24.13,-7.62; 2 -21.59,-7.62; 3 -19.05,-7.62; 4 -16.51,-7.62; 5 -13.97,-7.62; 6 -11.43,-7.62; 7 -8.89,-7.62; 8 -6.35,-7.62; 9 -3.81,-7.62; 10 -1.27,-7.62; 11 1.27,-7.62; 12 3.81,-7.62; 13 6.35,-7.62; 14 8.89,-7.62; 15 11.43,-7.62; 16 13.97,-7.62; 17 16.51,-7.62; 18 19.05,-7.62; 19 21.59,-7.62; 20 24.13,-7.62; 21 24.13,7.62; 22 21.59,7.62; 23 19.05,7.62; 24 16.51,7.62; 25 13.97,7.62; 26 11.43,7.62; 27 8.89,7.62; 28 6.35,7.62; 29 3.81,7.62; 30 1.27,7.62; 31 -1.27,7.62; 32 -3.81,7.62; 33 -6.35,7.62; 34 -8.89,7.62; 35 -11.43,7.62; 36 -13.97,7.62; 37 -16.51,7.62; 38 -19.05,7.62; 39 -21.59,7.62; 40 -24.13,7.62
DIL16 = drill 0.813 long: 1 -8.89,-3.81; 2 -6.35,-3.81; 3 -3.81,-3.81; 4 -1.27,-3.81; 5 1.27,-3.81; 6 3.81,-3.81; 7 6.35,-3.81; 8 8.89,-3.81; 9 8.89,3.81; 10 6.35,3.81; 11 3.81,3.81; 12 1.27,3.81; 13 -1.27,3.81; 14 -3.81,3.81; 15 -6.35,3.81; 16 -8.89,3.81
SOT23-6 = smd 0.6 x 1.4: 1 -0.95,-1.35; 2 0,-1.35; 3 0.95,-1.35; 4 0.95,1.35; 5 0,1.35; 6 -0.95,1.35
ICSP = drill 0.914 octagon: 1 -1.27,5.08; 2 1.27,5.08; 3 -1.27,2.54; 4 1.27,2.54; 5 -1.27,0; 6 1.27,0; 7 -1.27,-2.54; 8 1.27,-2.54; 9 -1.27,-5.08; 10 1.27,-5.08
W237-102 = drill 1.194 long: 1 -2.5,-1.27; 2 2.5,-1.27
DM3D_SD_MEMORY = smd 0.8 x 3: P$1 0,-1; P$2 1.1,-1; P$3 2.2,-1; P$4 3.3,-1; P$5 4.4,-1; P$6 5.5,-1; P$7 6.6,-1; P$8 7.7,-1
0805 = smd 1.2 x 1: 1 -1.1,0; 2 1.1,0
2312-RC = drill 1.6 square: P$1 0,-15.24; P$2 0,15.24
TO252 = smd 1 x 1.6: 1 -2.28,-4.8; 2 2.28,-4.8 | smd 5.4 x 6.2: 3 0,2.5
SOT23-BEC = smd 1 x 1.4: B -0.95,-1.1; C 0,1.1; E 0.95,-1.1
MPC70-2 = drill 1.118 pad 2.54 octagon: 1 -4.445,0; 2 4.445,0
MA06-1 = drill 1.016 long: 1 -6.35,0; 2 -3.81,0; 3 -1.27,0; 4 1.27,0; 5 3.81,0; 6 6.35,0
MA10-1 = drill 1.016 long: 1 -11.43,0; 2 -8.89,0; 3 -6.35,0; 4 -3.81,0; 5 -1.27,0; 6 1.27,0; 7 3.81,0; 8 6.35,0; 9 8.89,0; 10 11.43,0
MA10-2 = drill 1.016 octagon: 1 -11.43,-1.27; 2 -11.43,1.27; 3 -8.89,-1.27; 4 -8.89,1.27; 5 -6.35,-1.27; 6 -6.35,1.27; 7 -3.81,-1.27; 8 -3.81,1.27; 9 -1.27,-1.27; 10 -1.27,1.27; 11 1.27,-1.27; 12 1.27,1.27; 13 3.81,-1.27; 14 3.81,1.27; 15 6.35,-1.27; 16 6.35,1.27; 17 8.89,-1.27; 18 8.89,1.27; 19 11.43,-1.27; 20 11.43,1.27
TO220H = drill 1.118 long: 1 -2.54,-10.16; 2 0,-10.16; 3 2.54,-10.16 | hole 3.302: 0,4.826
PCB_RM2015S = hole 3.5: 9,70; 9,10; 89,10; 89,70
HS49S = drill 0.813 round: 1 -2.413,0; 2 2.413,0

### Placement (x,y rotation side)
C1  57.15,1.91 0 top
C2  40.64,2.54 180 top
C3  62.23,29.21 0 top
C4  3.17,6.35 180 top
C5  79.38,12.06 0 top
C6  62.87,34.29 180 top
C7  3.17,24.77 0 top
C8  12.7,26.67 0 top
C9  19.05,26.67 0 top
C10  24.77,26.67 0 top
C11  36.83,26.67 0 top
C12  95.25,29.84 270 top
C13  8.26,34.29 90 top
C14  19.05,43.18 0 top
C15  3.81,44.45 0 top
C16  17.78,48.26 0 top
C17  3.81,49.53 0 top
C18  27.94,55.88 180 top
C19  62.87,56.52 180 top
C20  22.86,64.77 90 top
C21  27.94,64.77 90 top
C22  77.47,67.94 0 top
C23  77.47,73.66 0 top
C24  8.26,76.2 180 top
C25  16.51,78.11 0 top
C100  80.01,43.18 180 bottom
C101  41.91,48.26 180 bottom
C102  48.26,48.26 180 bottom
C103  55.88,48.26 180 bottom
C104  50.16,78.11 0 bottom
D1  3.81,41.27 270 top
D2  26.67,50.8 0 top
D3  41.91,64.77 270 top
D4  52.07,68.58 180 top
D5  19.05,71.12 0 top
D6  82.55,72.39 90 top
D7  19.05,75.56 0 top
FB1  16.51,67.31 180 top
IC1  40.64,15.88 0 top
IC2  19.68,33.66 0 top
IC3  67.31,67.94 270 top
IC4  50.16,74.93 270 bottom
J1  90.17,45.72 0 top
J2  33.02,73.66 180 top
J3  60.96,73.66 180 top
J100  82.55,8.26 0 bottom
L1  3.17,21.59 180 top
L2  3.17,29.84 0 top
L3  45.72,43.18 90 top
L4  27.94,59.69 0 top
M1  68.58,62.23 90 top
Q1  85.09,63.5 270 top
R1  74.93,3.17 270 top
R2  77.47,3.17 270 top
R3  80.01,3.17 270 top
R4  72.39,6.99 0 top
R5  82.55,6.99 180 top
R6  72.39,10.79 0 top
R7  3.17,18.41 180 top
R8  3.81,38.1 0 top
R9  80.64,45.72 180 top
R10  22.86,50.8 90 top
R11  88.9,57.15 270 top
R12  77.47,58.42 0 top
R13  77.47,60.96 0 top
R14  81.28,64.77 90 top
R15  91.44,64.77 0 top
R16  82.55,69.85 180 top
R17  71.12,71.12 180 top
R18  2.54,73.03 270 top
R19  40.64,73.66 270 top
R20  43.18,73.66 270 top
R21  45.72,73.66 270 top
R22  71.12,74.93 180 top
R23  71.12,78.11 180 top
R100  80.01,48.26 180 bottom
R101  41.91,53.34 180 bottom
R102  48.26,53.34 180 bottom
R103  55.88,53.34 180 bottom
R104  80.01,53.34 0 bottom
R105  41.91,58.42 0 bottom
R106  48.26,58.42 0 bottom
R107  55.88,58.42 0 bottom
SV1  8.26,3.17 180 top
SV2  24.77,3.17 180 top
SV3  95.25,13.97 90 top
SV4  78.74,27.94 180 top
SV5  78.74,35.56 180 top
U1  11.43,46.99 0 top
U2  83.82,57.78 90 top
U3  12.7,59.69 270 top
U$1  0,0 0 top
X2  48.9,2.54 0 top

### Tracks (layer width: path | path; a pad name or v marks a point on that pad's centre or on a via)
+3V3  (via drill 0.51)
  Top 0.203: L4.1 27.43,59.31 27.81,58.93 27.81,50.29 27.3,49.78 D2.A 26.04,49.78 24.26,49.78 24.26,50.16 24,50.42 17.02,50.42 17.02,49.15 C16.1 | C16.1 14.1,48.26 U1.3 | C14.+ 17.53,43.94 17.02,44.45 17.02,47.37 C16.1 | v69.22,9.4 71.75,9.4 72.26,9.91 72.26,12.19 77.22,12.19 C5.1 | v89.15,3.05 v91.82,5.71 | v49.4,33.15 51.05,31.5 51.05,12.57 53.09,10.54 v53.09,6.35
  Bottom 0.203: v91.82,5.71 92.84,5.71 92.84,8.13 94.11,9.4 SV3.4 | v89.15,3.05 87.76,1.65 79.88,1.65 78.49,3.05 78.49,5.84 J100.P$5 78.11,8.64 77.6,9.14 69.47,9.14 v69.22,9.4 65.91,9.4 65.91,7.24 65.15,6.48 53.21,6.48 v53.09,6.35 | v49.4,33.15 46.74,33.15 44.7,35.18 22.48,35.18 22.48,38.23 18.16,42.55 C14.+
+5V  (via drill 0.51)
  Top 0.203: SV4.20 66.93,27.43 66.17,28.19 66.17,32.77 66.93,33.53 SV5.20 C6.1 64.52,35.18 64.52,39.12 | 64.52,39.12 62.1,39.12 58.8,35.81 58.8,31.37 60.07,30.1 C3.1 | 64.52,39.12 66.42,41.02 v66.42,49.91 66.42,54.23 65.02,55.63 C19.1 | C12.1 94.36,32 v94.36,33.02 v94.36,50.8 94.36,73.79 84.96,73.79 84.96,73.03 D6.A 83.57,71.75 82.93,71.12 v82.93,67.82 | SV1.5 4.7,4.7 4.7,5.46 C4.1 4.7,7.24 4.7,17.53 R7.1 4.32,19.3 4.32,21.21 L1.1 3.68,21.97 2.79,22.86 2.79,27.56 1.14,29.21 1.14,40.39 1.4,40.64 D1.A 2.16,41.91 2.16,43.56 C15.1 2.41,45.34 2.41,48.77 C17.+ U3.3 | U1.2 13.34,41.4 11.05,39.12 11.05,38.86 IC2.16 | IC3.3 65.28,67.18 v59.69,72.77 59.44,72.26 55.63,68.45 v55.63,66.93
  Bottom 0.203: 92.2,33.02 92.2,33.53 90.55,33.53 SV5.2 | 92.2,33.02 92.2,29.08 90.55,27.43 SV4.2 | v94.36,50.8 J1.2 90.81,50.42 90.04,49.66 88.52,49.66 88.39,49.78 66.55,49.78 v66.42,49.91 | v94.36,33.02 92.2,33.02 | 17.27,1.14 17.27,4.45 19.3,6.48 37.97,6.48 38.73,7.24 IC1.10 | 17.27,1.14 19.3,1.14 20.19,2.03 SV2.5 | 17.27,1.14 6.1,1.14 5.21,2.03 SV1.5 | IC2.16 10.54,38.86 2.79,46.61 2.79,48.77 C17.+ | v59.69,72.77 57.91,72.77 55.63,75.06 55.63,79.12 52.45,79.12 52.32,78.99 C104.1 | 17.72,67.37 7.87,57.53 4.19,57.53 U3.3 | 17.72,67.37 27.43,77.09 31.75,77.09 31.75,76.07 35.05,72.77 50.93,72.77 50.93,73.79 IC4.3 | 17.72,67.37 17.78,67.31 55.24,67.31 v55.63,66.93 56.13,66.67 68.83,66.67 72.9,62.61 78.99,62.61 78.99,63.88 v82.93,67.82
AGND  (via drill 0.51, 0.61)
  Top 0.203: L2.2 4.32,29.46 4.32,25.65 C7.2 5.33,25.65 v9.53,25.65 | v37.47,42.04 37.59,41.53 37.59,27.56 C11.2 38.99,25.78 38.99,25.02 39.12,24.89 IC1.31 | v33.53,45.21 33.53,60.58 26.16,60.58 25.91,60.33 25.91,56.77 C18.2
  Bottom 0.203: v33.53,45.21 36.45,42.29 36.96,42.29 v37.47,42.04 | v9.53,25.65 10.03,26.16 37.08,26.16 38.73,24.51 IC1.31
AREF
  Top 0.203: L4.2 29.08,59.31 29.08,56.77 C18.1
CLK1  (via drill 0.51)
  Top 0.203: R5.2 80.39,6.1 80.39,5.33 R3.1 80.9,3.94 80.9,3.56 v81.92,2.54
  Bottom 0.203: v81.92,2.54 79.63,2.54 79.63,5.84 J100.P$4 79.12,8.64 78.11,9.65 73.03,9.65 73.03,14.35 73.15,14.48 78.49,14.48 81.53,17.53 89.53,17.53 93.85,13.21 SV3.5
CLK2  (via drill 0.51)
  Top 0.203: v84.33,21.97 84.33,7.87 R5.1 | v71.63,23.5 71.63,25.78 70.99,26.42 70.99,27.69 70.23,28.45 SV4.17 | IC1.8 v34.29,20.83 | v92.58,27.43 92.58,49.4 91.06,49.4 90.3,48.64 90.3,44.83 89.28,43.81 J1.7
  Bottom 0.203: 84.33,23.88 v84.33,21.97 83.82,21.72 83.19,21.08 34.54,21.08 v34.29,20.83 | 84.33,23.88 81.66,23.88 81.28,23.5 v71.63,23.5 | v92.58,27.43 89.03,23.88 84.33,23.88
CS1  (via drill 0.51)
  Top 0.203: v71.63,2.54 74.04,4.95 R1.1 74.04,5.33 74.04,6.1 R4.2 74.55,7.87 74.55,8.38 81.92,8.38 82.17,8.13 82.17,5.97 82.8,5.33 82.8,1.65 91.57,1.65 92.08,2.16 93.73,2.16 SV3.1
  Bottom 0.203: v71.63,2.54 72.52,3.43 75.56,3.43 75.56,5.84 J100.P$7
CS2  (via drill 0.51)
  Top 0.203: 68.2,17.4 68.2,21.84 68.71,22.35 v68.71,23.5 | 68.2,17.4 68.2,7.87 70.23,7.87 R4.1 | v75.18,24.38 76.33,25.53 76.33,27.69 77.09,28.45 SV4.11 | v25.4,16 23.11,13.72 23.11,7.11 23.5,6.73 23.5,6.35 25.15,6.35 26.04,7.24 IC1.5 | v68.58,17.4 68.2,17.4
  Bottom 0.203: v68.71,23.5 69.6,24.38 v75.18,24.38 | v25.4,16 26.42,17.02 68.2,17.02 v68.58,17.4
GND  (via drill 0.51)
  Top 0.203: FB1.2 15.24,67.31 | C6.2 61.72,35.18 61.72,38.1 62.23,38.61 63.5,38.61 v63.5,36.7 63.5,35.69 63.25,35.43 63.25,30.1 C3.2 | v59.31,54.23 60.71,55.63 C19.2 62.1,57.4 62.1,57.91 65.15,57.91 68.2,54.86 68.2,52.58 | v52.32,29.46 51.56,30.23 51.56,34.92 49.4,37.08 v49.4,43.81 | 68.2,52.58 68.2,38.1 67.69,37.59 SV5.19 | R10.1 21.97,48.64 19.94,48.64 C16.2 19.94,47.37 20.07,47.24 20.07,43.94 C14.- 19.56,42.93 16.51,39.88 13.59,39.88 13.59,38.86 IC2.15 12.7,36.45 12.7,35.69 9.14,35.69 C13.2 | v27.05,39.37 27.05,27.69 26.92,27.56 C10.2 | 2.16,35.05 2.16,37.21 R8.1 | 2.16,35.05 2.16,30.23 L2.1 | 2.16,35.05 7.37,35.05 C13.2 | C13.2 9.14,36.45 9.14,41.4 U1.1 8.76,42.93 5.97,42.93 5.97,43.56 C15.2 5.08,45.34 C17.- 5.08,59.31 4.95,59.69 | IC3.1 65.28,69.09 60.07,74.3 60.07,75.95 56.64,79.38 18.67,79.38 18.67,78.99 C25.2 | C4.2 1.78,5.46 1.78,4.7 SV1.6 | C2.2 39.88,3.43 41.66,5.21 41.66,6.86 IC1.11 | R14.1 82.17,62.61 83.31,62.61 Q1.E 84.58,62.1 v87.12,62.1 | J1.4 J1.6 J1.8 J1.10 91.06,40.01 91.06,38.1 90.55,37.59 SV5.1 90.55,36.07 91.31,35.31 v91.31,30.99 | v80.9,24.38 80.9,12.95 C5.2 | C12.2 96.14,27.69 97.28,26.54 97.28,16.89 96.39,16 SV3.6 | SV3.6 96.39,14.48 97.28,13.59 97.28,9.27 96.39,8.38 SV3.3 96.39,6.86 97.28,5.97 97.28,1.52 v96.9,1.14 80.9,1.14 R3.2 79.12,1.78 78.36,1.78 R2.2 76.58,1.78 75.82,1.78 R1.2 74.04,1.02 74.04,0.76 68.2,0.76 67.94,1.02 59.31,1.02 C1.2 57.91,2.79 v56.9,3.81 | SV4.1 89.79,28.45 89.03,27.69 89.03,21.08 94.11,16 SV3.6 | 68.2,52.58 79.25,52.58 v83.19,48.64
  Top 0.254: C24.- 6.6,75.56 4.95,73.91 4.95,59.69
  Top 0.61: C25.2 18.41,78.11 18.41,73.03 14.61,69.22 14.61,67.31
  Top 1.016: FB1.2 14.61,67.31 14.61,59.69 4.95,59.69 U3.2
  Bottom 0.203: v63.5,36.7 66.55,36.7 SV5.19 | C103.2 57.4,49.15 57.4,52.45 R103.2 | v59.31,54.23 58.04,54.23 R103.2 | 43.43,50.8 43.43,52.45 R101.2 | 43.43,50.8 43.43,49.15 C101.2 42.67,47.37 41.91,46.61 25.91,46.61 22.23,42.93 | 49.78,51.44 49.78,52.45 R102.2 | 49.78,51.44 49.78,50.8 | 49.78,50.8 49.78,49.15 C102.2 49.02,47.37 48.39,47.37 48.39,44.83 v49.4,43.81 | v52.32,29.46 66.55,29.46 SV4.19 | 49.78,50.8 43.43,50.8 | 49.78,51.44 55.63,51.44 56.64,52.45 R103.2 | v27.05,39.37 23.5,42.93 22.23,42.93 | 22.23,42.93 21.08,42.93 C14.- | IC4.1 50.93,76.07 49.78,77.22 49.4,77.22 C104.2 48.01,78.99 47.88,79.12 10.41,79.12 7.75,76.45 C24.- | 22.1,5.97 40.01,5.97 41.27,7.24 IC1.11 42.55,7.24 45.97,3.81 v56.9,3.81 | 22.1,5.97 20.83,5.97 19.18,4.32 SV2.6 | 22.1,5.97 22.1,1.91 20.83,0.64 4.06,0.64 2.67,2.03 SV1.6 | 81.53,44.07 81.53,47.37 R100.2 | v87.12,62.1 88.39,60.83 90.93,60.83 95.25,56.52 95.25,48.9 91.82,48.9 J1.4 90.81,47.88 90.04,47.12 82.42,47.12 82.17,47.37 R100.2 | v80.9,24.38 82.04,25.53 88.14,25.53 89.03,26.42 89.03,28.32 89.15,28.32 89.53,28.7 SV4.1 90.3,29.97 v91.31,30.99 | v96.9,1.14 94.23,1.14 91.44,3.94 80.64,3.94 80.64,5.84 J100.P$3 | v83.19,48.64 82.17,48.64 R100.2
  Bottom 0.254: 81.53,44.07 C100.2
GND1  (via drill 1.6)
  Top 0.203: FB1.1 17.78,67.31 | C20.2 22.86,66.04 | U2.3 84.58,58.93 81.41,62.1 80.01,62.1 80.01,62.36 79.63,62.74 79.63,67.06 C22.2 78.74,68.83 C23.-
  Top 1.016: FB1.1 18.41,67.31 18.41,66.27 C20.2
  Top 1.778: C20.2 27.94,66.27 | 27.94,66.27 C21.- | J2.2 30.48,74.93 30.48,66.27 27.94,66.27
  Top 2.54: J3.2 54.61,74.93 54.61,74.65 D4.1 53.98,74.65 | 53.98,74.65 D4.3 | v53.98,77.47 53.98,74.65
  Bottom 0.203: C23.- 78.49,72.9 78.49,63.12 73.03,63.12 69.34,66.8 69.34,69.85 70.36,69.85 71.12,70.61 71.12,79.38 62.48,79.38 59.31,76.2 J3.2
  Bottom 2.54: J2.2 30.48,74.93 30.48,71.12 53.98,71.12 v53.98,77.47
IBAT  (via drill 0.51)
  Top 0.203: v25.02,46.99 25.02,25.53 24.38,24.89 IC1.37 24.38,22.1 24.38,18.54 v26.8,16.13 | v70.74,25.27 69.6,24.13 69.6,16.64 v69.09,16.13
  Bottom 0.203: R105.2 40.51,57.53 40.51,54.23 R101.1 40.51,52.45 40.51,49.15 C101.1 39.75,47.37 25.4,47.37 v25.02,46.99 | v70.74,25.27 78.23,25.27 79.25,26.29 SV4.10 | v69.09,16.13 68.71,16.51 27.18,16.51 v26.8,16.13
IIN-  (via drill 0.51, 1.6)
  Top 0.203: R17.1 72.39,71.12 72.39,64.77 73.38,64.77 | 76.2,68.58 C22.1 73.66,67.94 | R11.2 88.01,56.39 88.01,56.64 85.85,56.64 U2.1 84.58,56.64 83.57,55.63 77.47,55.63 77.47,63.5 v76.2,64.77 | v70.23,68.96 69.34,68.96 IC3.6 | C23.+ 75.56,73.28 74.42,72.14 73.66,71.12
  Top 1.778: R23.1 R22.1 R17.1
  Top 2.54: 73.38,64.77 73.66,64.77 73.66,67.94 73.66,71.12 | 73.38,64.77 M1.2 | v76.2,64.77 73.38,64.77 | v74.93,78.11 73.66,78.11
  Bottom 0.203: 73.66,68.96 v70.23,68.96
  Bottom 1.778: 73.66,71.12 72.39,71.12 72.39,78.11 73.66,78.11
  Bottom 2.54: v76.2,64.77 73.66,64.77 73.66,68.96 73.66,71.12 | 73.66,78.11 v74.93,78.11
IOUT+  (via drill 0.51)
  Top 0.203: v38.73,74.93 39.24,74.42 39.24,73.41 39.75,72.9 R19.2
  Top 0.254: D3.4 43.31,62.1
  Top 1.778: 43.18,71.12 R20.2 43.18,72.39 | R21.2 45.72,72.39 43.18,72.39 | R19.2 40.64,72.39 43.18,72.39
  Top 2.54: D3.4 43.14,71.12 43.18,71.12
  Bottom 0.203: v38.73,74.93 47.37,74.93 48.13,74.17 IC4.4
IPANEL  (via drill 0.51)
  Top 0.203: v32.89,25.27 33.15,25.53 33.15,37.72 v36.45,41.02 | v67.31,41.53 v67.31,48.9 | v83.95,41.53 83.95,28.19 84.71,27.43 SV4.6
  Bottom 0.203: 78.74,43.18 C100.1 79.25,42.29 79.76,41.78 83.69,41.78 v83.95,41.53 | 78.61,44.07 78.61,47.37 R100.1 77.85,49.02 67.31,49.02 | 67.31,49.02 65.53,49.02 65.53,50.29 66.04,50.8 76.2,50.8 77.85,52.45 R104.2 | v32.89,25.27 20.45,25.27 19.68,24.51 IC1.39 | v36.45,41.02 53.59,41.02 54.1,41.53 v67.31,41.53 | v67.31,48.9 67.31,49.02
  Bottom 0.254: 77.85,43.81 C100.1 78.61,44.07
MISO  (via drill 0.51)
  Top 0.203: v33.4,14.73 33.4,11.05 32,9.65 IC1.7 | v85.72,19.18 v85.72,16.64 | J1.9 89.03,40.01 89.03,32 91.69,29.34 91.69,20.95 94.11,18.54 SV3.7 | v72.52,43.81 68.71,40.01 68.71,30.86 70.36,30.86 71.63,29.59 SV4.15 | v83.69,43.81 v76.83,43.81
  Bottom 0.203: v33.4,14.73 72.52,14.73 75.44,17.65 75.44,19.18 v85.72,19.18 92.71,19.18 93.73,18.16 SV3.7 | v85.72,16.64 84.96,16.64 84.96,13.97 83.06,12.06 81.79,12.06 81.79,8.64 J100.P$2 | v76.83,43.81 v72.52,43.81 | v83.69,43.81 86.49,41.02 88.27,41.02 J1.9
MOSI1  (via drill 0.51)
  Top 0.203: 70.93,4.51 69.34,2.92 69.34,2.16 69.85,1.65 73.53,1.65 73.53,2.54 | 70.93,4.51 72.01,5.59 72.01,8.76 73.15,9.91 R6.2 | 73.53,2.54 74.55,3.56 76.58,3.56 76.58,3.94 R2.1 | 73.53,2.54 v73.03,2.54 | v82.8,22.86 82.8,5.97 86.11,2.67 86.11,2.16 91.44,2.16 93.85,4.57 SV3.2 | v67.69,22.61 67.69,7.75 70.93,4.51
  Bottom 0.203: v73.03,2.54 76.71,2.54 76.71,5.84 J100.P$6 | v82.8,22.86 72.26,22.86 72.01,22.61 v67.69,22.61
MOSI2  (via drill 0.51)
  Top 0.203: v78.87,24.38 78.87,22.35 71.75,15.24 71.75,11.81 71.63,11.68 R6.1 v69.22,10.79 | v79.63,50.67 75.95,46.99 75.95,37.47 76.07,37.34 76.07,30.73 75.31,29.97 SV4.13
  Bottom 0.203: v78.87,24.38 80.01,25.53 80.52,25.53 81.15,26.16 81.15,28.07 76.45,28.07 75.69,28.83 SV4.13 | v69.22,10.79 31.37,10.79 29.84,9.27 IC1.6 | v79.63,50.67 88.27,50.67 J1.1
N$1
  Top 0.254: C25.1 14.73,77.22 14.35,76.83 14.35,76.33 D7.C
  Top 1.016: R18.1 2.54,78.74 9.53,78.74 C24.+ 9.53,75.56 D7.C D5.C
N$2
  Top 0.203: C9.1 18.16,27.56 18.16,28.45 IC2.4
N$3
  Top 1.016: U3.1 R18.2
N$4
  Top 0.203: C9.2 20.7,27.56 20.7,28.45 IC2.5
N$5
  Top 0.203: D1.C 5.59,40.64 5.59,38.99 R8.2
N$6
  Top 0.203: D2.C 26.04,52.58 23.75,52.58 R10.2
N$7  (via drill 0.51)
  Top 0.203: L1.2 2.16,21.97 2.16,23.88 C7.1 1.91,25.65 v1.91,26.67
  Bottom 0.203: v1.91,26.67 39.12,26.67 41.27,24.51 IC1.30
N$8
  Top 0.203: U2.6 82.3,57.02
  Top 0.406: 82.7,56.84 U2.6
  Top 0.61: 81.92,56.52 82.7,56.84
  Top 0.813: R13.2 78.74,60.96 78.74,56.52 81.92,56.52
N$9
  Top 0.203: D6.C 80.9,71.75 80.9,70.74 R16.2
N$10  (via drill 0.51)
  Top 0.203: R14.2 82.17,66.04 83.31,64.9 Q1.B 84.07,64.9 v84.07,65.79 | v85.98,65.41 89.28,65.41 R15.1
  Bottom 0.203: v85.98,65.41 85.6,65.79 v84.07,65.79
N$11
  Top 0.203: C8.2 14.86,27.56 15.62,28.32 15.62,28.45 IC2.3
N$12  (via drill 0.51)
  Top 0.203: v38.23,73.66 38.35,73.53 38.35,61.98 v40.01,60.33
  Bottom 0.203: v38.23,73.66 38.61,73.28 49.91,73.28 49.91,73.91 50.67,74.68 50.93,74.68 IC4.2 | v40.01,60.33 40.51,59.82 42.16,59.82 42.67,59.31 R105.1
N$13
  Top 0.203: C8.1 11.05,27.56 11.05,28.45 IC2.1
N$14  (via drill 0.51)
  Top 0.203: v73.79,54.74 69.98,58.55 69.98,65.28 68.83,65.28 67.56,66.55 67.56,67.69 66.55,67.69 IC3.2
  Bottom 0.203: v73.79,54.74 80.26,54.74 80.77,54.23 R104.1
N$15
  Top 0.203: X2.1 C2.1 42.8,3.43 42.8,5.46 44.2,6.86 IC1.12
N$16
  Top 0.203: U2.4 81.79,58.8 79.63,58.8 R12.2
  Top 0.254: U2.4 82.3,58.8
N$17
  Top 0.203: C1.1 54.99,2.29 51.94,2.29 X2.2 51.05,3.17 51.05,3.3 47.37,6.99 IC1.13
N$18  (via drill 0.51)
  Top 0.203: R7.2 2.41,17.53 3.3,16.64 3.3,1.91 4.57,0.64 36.32,0.64 36.32,7.11 IC1.9 37.08,9.65 37.08,16.38 42.93,22.23 42.93,53.21 v44.83,55.12 | v76.83,46.61 78.49,46.61 R9.2
  Bottom 0.203: v76.83,46.61 75.44,48.01 65.91,48.01 60.2,53.72 60.2,55.12 56.9,55.12 55.5,53.72 55.5,51.94 53.34,51.94 50.29,54.99 44.96,54.99 v44.83,55.12
N$19  (via drill 0.51)
  Top 0.203: v35.18,19.81 35.18,21.46 34.54,22.1 IC1.33 | v64.64,19.43 66.8,21.59 66.8,23.24 69.47,25.91 SV4.18
  Bottom 0.203: v35.18,19.81 35.56,19.43 46.48,19.43 47.24,20.19 59.56,20.19 60.33,19.43 v64.64,19.43
N$20  (via drill 0.51)
  Top 0.203: v32.38,13.84 32.38,21.72 32,22.1 IC1.34 | v69.09,13.84 72.52,17.27 72.52,25.91 SV4.16
  Bottom 0.203: v32.38,13.84 v69.09,13.84
N$21
  Top 0.203: M1.1 73.66,59.69
  Top 0.813: R12.1 76.2,58.42 76.2,59.69 | 73.66,59.69 76.2,59.69 | R13.1 76.2,60.96 76.2,59.69
N$22  (via drill 0.51)
  Top 0.203: v29.34,15.62 29.34,22.1 IC1.35 | v60.2,15.62 v62.87,12.95 | v69.09,12.45 71.25,14.61 71.25,15.37 74.3,18.41 74.3,26.16 SV4.14
  Bottom 0.203: v29.34,15.62 v60.2,15.62 | v62.87,12.95 63.37,12.45 v69.09,12.45
N$23  (via drill 0.51)
  Top 0.203: v26.8,20.83 26.8,22.1 IC1.36 | v40.51,18.54 43.43,21.46 43.43,32.51 47.5,36.58 v47.5,55.88 | v75.95,56.52 80.39,52.07 84.71,52.07 84.71,43.56 81.15,40.01 81.15,28.7 80.26,27.81 77.85,27.81 77.85,27.43 SV4.12
  Bottom 0.203: v26.8,20.83 29.08,18.54 v40.51,18.54 | v47.5,55.88 48.64,57.02 50.8,57.02 53.59,59.82 55.24,59.82 56.26,58.8 56.26,56.52 v75.95,56.52
N$24
  Top 0.203: U2.5 U2.2 85.85,57.91 88.01,57.91 R11.1 88.01,59.31 88.01,63.12 86.87,63.12 Q1.C 85.6,63.88 85.6,64.52 84.96,65.15 84.96,68.71 84.71,68.96 R16.1
N$25
  Top 2.54: 40.64,76.2 45.72,76.2
N$26  (via drill 0.51)
  Top 0.203: v66.8,8.51 v66.8,19.3
  Bottom 0.203: v66.8,8.51 69.6,8.51 69.72,8.64 74.55,8.64 J100.P$8 | v66.8,19.3 68.07,20.57 91.82,20.57 93.73,22.48 SV3.9
N$27  (via drill 0.51)
  Top 0.203: v17.14,19.56 17.14,10.03 16.76,9.65 IC1.1
  Bottom 0.203: v17.14,19.56 19.3,21.72 47.37,21.72 48.51,22.86 48.51,30.35 86.11,30.35 86.87,29.59 SV4.3
N$28
  Top 0.203: C10.1 23.37,27.56 23.37,28.45 IC2.6
N$29
  Bottom 0.203: J100.P$1 82.93,5.84 83.57,5.21 91.06,5.21 91.44,4.83 92.58,4.83 94.23,6.48 96.52,6.48 97.28,7.24 97.28,19.56 96.39,19.56 SV3.8
N$30  (via drill 1.6)
  Top 1.778: 55.88,62.23 v55.88,64.77 | 60.96,62.23 v60.96,64.77
  Top 2.54: 58.42,62.23 55.88,62.23 53.34,62.23 53.34,67.31 52.07,67.31 D4.4 52.07,43.18 L3.P$1 v64.77,43.18 | 58.42,62.23 60.96,62.23 M1.3 | 58.42,62.23 58.99,62.23 | v55.88,64.77 54.61,64.77
N$31  (via drill 0.51)
  Top 0.203: v11.43,32.13 9.14,32.13 C13.1
  Bottom 0.203: v11.43,32.13 12.7,30.86 IC2.2
N$32  (via drill 0.51)
  Top 0.203: v25.91,33.78 25.91,36.07 IC2.10 | v21.21,33.02 19.43,31.24 19.43,26.04 18.03,24.64 18.03,5.21 15.75,2.92 15.75,1.91 14.99,1.14 9.91,1.14 9.91,1.65 SV1.3
  Bottom 0.203: v25.91,33.78 25.15,33.02 v21.21,33.02
N$33  (via drill 0.51)
  Top 0.203: v28.83,32.89 28.83,36.07 IC2.9 | v13.46,32.13 12.32,30.99 12.32,21.46 v5.59,14.73
  Bottom 0.203: v28.83,32.89 28.07,32.13 v13.46,32.13 | v5.59,14.73 4.95,14.1 4.95,5.08 5.46,5.08 6.22,4.32 SV1.4
N$34  (via drill 1.6)
  Top 0.254: 35.84,63.5 34.67,63.5
  Top 1.778: C20.1 27.94,63.27 C21.+ v33.02,63.5
  Top 2.54: 35.84,67.31 D3.1 35.84,63.5 D3.3 35.84,62.23 35.56,62.23 35.56,43.18 L3.P$2 v26.67,43.18 | v33.02,63.5 34.67,63.5 35.56,63.5
N$35  (via drill 0.51, 1.6)
  Top 0.203: v49.02,61.34 47.37,62.99 47.37,73.53 46.61,74.3
  Top 0.254: R21.1 46.61,74.3
  Top 1.778: R21.1 45.72,74.93 43.18,74.93 | R19.1 40.64,74.93 43.18,74.93 | 43.18,74.93 R20.1 | 43.18,76.2 43.18,74.93 | 43.18,77.47 v45.72,77.47 | D7.A 24.13,78.11 35.56,78.11 35.56,77.47
  Top 2.54: J2.1 35.52,77.47 35.56,77.47 43.18,77.47 43.18,76.2
  Bottom 0.203: IC4.6 48.13,76.07 47.88,76.33 46.86,76.33 v45.72,77.47 | v49.02,61.34 49.02,59.31 R106.1
  Bottom 2.54: 35.56,74.93 35.56,77.47 v45.72,77.47
N$36  (via drill 0.51)
  Top 0.203: v15.49,19.94 15.49,26.8 16.89,28.19 16.89,35.31 16.13,36.07 IC2.14 | v28.19,13.21 28.19,6.99 30.61,4.57 SV2.1
  Bottom 0.203: v15.49,19.94 22.23,13.21 v28.19,13.21
N$37  (via drill 0.51)
  Top 0.203: v27.94,33.91 27.56,33.53 27.56,24.77 27.69,24.64 27.69,13.97 27.3,13.59 27.3,9.78 27.69,9.4 27.69,5.21 28.19,4.7 SV2.2
  Bottom 0.203: v27.94,33.91 27.18,34.67 20.83,34.67 19.05,36.45 IC2.13
N$38  (via drill 0.51)
  Top 0.203: v34.04,28.57 34.16,28.45 34.16,25.65 34.54,25.27 35.81,25.27 35.81,20.45 36.07,20.19 36.07,9.65 35.31,8.89 v35.31,5.08
  Bottom 0.203: v34.04,28.57 33.53,28.07 27.43,28.07 26.67,28.83 IC2.7 | v35.31,5.08 35.18,5.21 27.69,5.21 26.8,4.32 SV2.3
N$39  (via drill 0.51)
  Top 0.203: v32.77,2.41 32.77,3.94 30.23,6.48 30.23,27.05 28.83,28.45 IC2.8
  Bottom 0.203: v32.77,2.41 31.5,1.14 25.15,1.14 24.26,2.03 SV2.4
N$40  (via drill 1.4)
  other vias: 2.54,64.77
N$62  (via drill 0.51)
  Top 0.203: v22.61,15.88 22.61,12.95 19.3,9.65 IC1.2 | v51.94,17.91 53.59,16.26 53.59,7.11 56.01,4.7 68.58,4.7 v68.58,1.65 | v91.06,3.05 92.84,4.83 92.84,16.64 86.23,23.24 86.23,27.69 85.47,28.45 SV4.5
  Bottom 0.203: v22.61,15.88 24.38,17.65 51.69,17.65 v51.94,17.91 | v68.58,1.65 69.09,1.14 89.15,1.14 v91.06,3.05
N$65
  Top 2.54: 40.64,71.12 45.72,71.12 45.72,67.31 40.64,67.31 40.64,71.12 | 40.64,71.12 44.45,71.12 44.45,68.58 41.91,68.58 41.91,69.85
N$66
  Top 2.54: 64.77,63.5 60.96,63.5 60.96,60.96 63.5,60.96
N$67  (via drill 0.51)
  Top 0.203: v35.43,1.52 35.43,1.14 28.19,1.14 27.18,2.16 27.18,5.21 24,5.21 22.1,7.11 IC1.3 | v70.23,2.54 72.77,5.08 72.77,8.13 74.04,9.4 79.76,9.4 79.76,24.77 81.41,26.42 81.41,27.69 82.17,28.45 SV4.7
  Bottom 0.203: v35.43,1.52 66.55,1.52 67.56,2.54 v70.23,2.54
N$68  (via drill 0.51)
  Top 0.203: v26.8,14.35 26.8,12.06 24.38,9.65 IC1.4 | v31.11,14.73 30.73,15.11 v30.73,28.96 | v77.09,31.75 79.25,29.59 SV4.9
  Bottom 0.203: v26.8,14.35 27.18,14.73 v31.11,14.73 | v30.73,28.96 33.15,31.37 63.63,31.37 64.9,32.64 73.03,32.64 73.91,31.75 v77.09,31.75
N$69  (via drill 0.51)
  Top 0.203: v54.74,17.91 54.74,9.65 IC1.16
  Bottom 0.203: v54.74,17.91 55.24,18.41 70.36,18.41 72.01,20.07 92.58,20.07 94.23,21.72 96.52,21.72 97.28,22.48 97.28,39.12 85.22,39.12 83.31,37.21 SV5.7
N$70  (via drill 0.51)
  Top 0.203: v56.52,19.3 56.52,10.03 56.9,9.65 IC1.17 | v47.62,19.3 48.01,19.68 48.01,53.85 v50.04,55.88 | v69.09,51.69 74.17,46.61 v74.17,41.53 | v79.38,39.62 79.63,39.37 79.63,37.59 SV5.9
  Bottom 0.203: v56.52,19.3 v47.62,19.3 | v50.04,55.88 50.29,56.13 54.48,56.13 54.99,55.63 65.15,55.63 v69.09,51.69 | v74.17,41.53 75.18,40.51 78.49,40.51 v79.38,39.62
N$71  (via drill 0.51)
  Top 0.203: v59.69,33.15 61.85,30.99 61.85,25.02 61.98,24.89 IC1.22
  Bottom 0.203: v59.69,33.15 61.98,35.43 77.98,35.43 78.87,34.54 78.87,33.15 86.11,33.15 86.87,33.91 SV5.4
N$72  (via drill 0.51)
  Top 0.203: v58.17,38.23 58.17,26.16 59.44,24.89 IC1.23 | v42.04,38.23 42.42,38.61 42.42,54.1 48.77,60.45 50.04,60.45 v50.04,63.12 | v90.81,58.17 93.47,55.5 v93.47,38.23
  Bottom 0.203: v42.04,38.23 v58.17,38.23 | v50.04,63.12 50.42,62.74 72.14,62.74 74.55,60.33 88.65,60.33 v90.81,58.17 | v93.47,38.23 90.68,35.43 86.61,35.43 85.85,34.67 SV5.6
N$73  (via drill 0.51)
  Top 0.203: v57.28,39.24 57.28,37.85 57.66,37.47 57.66,25.15 57.4,24.89 IC1.24
  Bottom 0.203: v57.28,39.24 57.4,39.12 61.34,39.12 61.85,38.61 79.88,38.61 81.41,37.08 81.41,35.05 82.17,35.05 SV5.8
N$74  (via drill 0.51)
  Top 0.203: v77.98,39.62 78.87,38.73 78.87,35.81 79.63,35.05 SV5.10 | IC1.25 v54.61,40.13
  Bottom 0.203: v54.61,40.13 60.96,40.13 61.85,39.24 77.6,39.24 v77.98,39.62
N$75  (via drill 0.51)
  Top 0.203: v53.21,40.01 53.21,25.78 52.32,24.89 IC1.26 | v71.88,40.13 73.79,38.23 v73.79,33.15
  Bottom 0.203: v53.21,40.01 54.23,41.02 60.71,41.02 61.98,39.75 71.5,39.75 v71.88,40.13 | v73.79,33.15 75.95,33.15 76.71,33.91 SV5.12
N$76  (via drill 0.51)
  Top 0.203: v73.53,28.07 73.79,28.32 73.79,31.88 74.68,32.77 74.68,33.53 SV5.14
  Bottom 0.203: v73.53,28.07 53.72,28.07 50.16,24.51 IC1.27
N$77  (via drill 0.51)
  Top 0.203: v47.12,32.26 47.12,24.89 IC1.28
  Bottom 0.203: v47.12,32.26 63.75,32.26 64.64,33.15 70.87,33.15 71.63,33.91 SV5.16
N$78  (via drill 0.51)
  Top 0.203: v47.12,34.04 46.23,33.15 46.23,26.42 44.7,24.89 IC1.29 | v59.56,37.85 v62.36,40.64 | v70.61,40.64 70.99,40.26 70.99,35.81 70.23,35.05 SV5.18
  Bottom 0.203: v47.12,34.04 49.4,36.32 58.04,36.32 v59.56,37.85 | v62.36,40.64 v70.61,40.64
N$79  (via drill 0.51)
  Top 0.203: v48.26,9.91 48.51,10.16 48.51,44.45 v49.28,45.21 | v76.83,41.91 77.09,41.66 77.09,37.59 SV5.11
  Bottom 0.203: v48.26,9.91 48.39,10.03 58.29,10.03 59.05,9.27 IC1.18 | v49.28,45.21 49.53,45.47 57.15,45.47 57.78,46.1 68.96,46.1 72.14,42.93 75.82,42.93 v76.83,41.91
N$80  (via drill 0.51)
  Top 0.203: v65.28,31.75 65.28,28.57 63.75,27.05 63.75,10.41 64.52,9.65 IC1.20 | v69.6,31.75 71.25,33.4 71.25,35.31 72.01,36.07 SV5.15
  Bottom 0.203: v65.28,31.75 v69.6,31.75
N$81  (via drill 0.51)
  Top 0.203: v62.87,26.29 62.61,26.54 v62.61,37.72
  Bottom 0.203: v62.87,26.29 64.39,24.77 IC1.21 | v62.61,37.72 62.87,37.97 68.33,37.97 69.09,37.21 SV5.17
PWM  (via drill 0.51)
  Top 0.203: v92.2,58.29 92.2,63.88 R15.2 | v78.23,50.67 75.31,47.75 75.31,46.61 | 75.31,46.61 75.31,37.59 SV5.13 | v56.01,33.15 55.88,33.02 55.88,26.8 56.13,26.54 56.13,22.35 57.4,21.08 57.4,14.22 61.98,9.65 IC1.19 | v52.32,35.43 50.29,37.47 50.29,46.1 v50.04,46.35 | v75.06,46.61 75.31,46.61
  Bottom 0.203: v92.2,58.29 85.47,51.56 79.12,51.56 v78.23,50.67 | v56.01,33.15 53.72,35.43 v52.32,35.43 | v50.04,46.35 50.29,46.61 v75.06,46.61
RESET  (via drill 0.51)
  Top 0.203: R9.1 v83.82,45.72
  Bottom 0.203: v83.82,45.72 J1.5
RXD1  (via drill 0.51)
  Top 0.203: IC2.12 20.32,38.48 19.43,39.37 14.35,39.37 14.35,28.7 13.72,28.07 12.83,28.07 12.83,4.32 SV1.2 | v49.4,12.19 49.4,9.65 IC1.14 | v85.72,53.09 85.72,39.12 87.25,37.59 SV5.3
  Bottom 0.203: v49.4,12.19 49.28,12.32 17.14,12.32 12.83,8 12.83,4.7 12.45,4.7 SV1.2 | v85.72,53.09 78.99,59.82 55.88,59.82 53.47,62.23 35.18,62.23 16.64,43.69 16.64,39.24 19.56,39.24 20.32,38.48 IC2.12
TXD1  (via drill 0.51)
  Top 0.203: v18.92,10.54 18.92,13.46 22.61,17.14 22.61,25.27 24.13,25.27 24.51,25.65 24.51,35.31 23.75,36.07 IC2.11 | v50.67,11.68 50.67,10.79 51.82,9.65 IC1.15 | v84.84,40.01 84.84,37.59 SV5.5 | v45.59,42.04 43.81,40.26 v43.81,37.34
  Bottom 0.203: SV1.1 15.37,4.32 16.38,5.33 17.53,5.33 17.53,9.14 v18.92,10.54 19.43,10.79 19.94,11.3 50.29,11.3 v50.67,11.68 | v84.84,40.01 84.2,40.64 78.99,40.64 78.61,41.02 75.95,41.02 74.55,42.42 68.45,42.42 66.17,44.7 59.31,44.7 56.64,42.04 v45.59,42.04 | v43.81,37.34 42.16,35.69 24.89,35.69 24.13,36.45 IC2.11
VBAT  (via drill 0.51)
  Top 0.203: v45.21,49.91 v45.21,51.69 45.72,51.94 45.72,55.5 v46.1,55.88 | v24.13,43.56 22.1,41.53 22.1,25.15 21.84,24.89 IC1.38 | v81.79,21.97 81.79,25.53 82.17,25.91 SV4.8 | v56.77,27.18 56.9,27.3 56.9,37.59 56.39,38.1 56.39,39.62 54.99,41.02 51.18,41.02 v51.18,40.13
  Bottom 0.203: v45.21,49.91 45.34,49.91 46.1,49.15 C102.1 46.1,47.37 44.83,46.1 32.64,46.1 | v45.21,51.69 45.97,52.45 46.1,52.45 R102.1 | v46.1,55.88 46.1,57.53 R106.2 | v24.13,43.56 26.67,46.1 32.64,46.1 | v81.79,21.97 81.53,21.72 67.31,21.72 65.79,23.24 65.79,27.18 v56.77,27.18 | v51.18,40.13 36.07,40.13 32.64,43.56 32.64,46.1
VDD
  Top 0.203: C11.1 36.07,25.78 36.58,25.27 36.58,24.89 IC1.32
VIN  (via drill 0.51, 1.6)
  Top 0.203: 69.7,72.39 69.85,72.39 | 70.87,67.18 71.12,67.18 71.12,69.47 70.36,70.23 R17.2 | 70.87,67.18 69.34,67.18 IC3.4 | 70.87,67.18 v70.87,58.93
  Top 1.016: 68.58,72.39 69.85,72.39 69.85,71.12 69.85,78.11
  Top 1.27: 68.58,71.75 69.85,71.75 69.85,71.12
  Top 1.778: R22.2 69.85,74.93 | 68.58,74.93 R22.2 | 69.85,78.11 R23.2 | R22.2 69.7,72.39 R17.2 69.85,71.12
  Top 2.54: J3.1 68.58,74.93 | v67.31,72.39 v67.31,77.47 | R23.2 68.58,78.11 68.58,72.39
  Bottom 0.203: v70.87,58.93 58.04,58.93 R107.1
  Bottom 0.254: 48.39,68.58 48.39,67.82
  Bottom 1.778: 68.58,74.93 69.85,74.93 | 69.85,74.93 69.85,78.11 | 69.85,74.93 69.85,71.12 | D5.A 24.13,68.58 48.39,68.58 63.5,68.58 63.5,74.93
  Bottom 2.54: J3.1 63.5,74.93 67.31,74.93 | 67.31,74.93 68.58,74.93 | 67.31,74.93 v67.31,72.39 | 67.31,74.93 v67.31,77.47
VPANEL  (via drill 0.51)
  Top 0.203: v58.17,45.21 56.13,47.24 v56.13,50.16 55.88,50.67 55.88,53.47 v54.1,55.24 v55.37,56.52 | v41.53,42.93 41.15,42.55 v41.15,27.56
  Bottom 0.203: 58.17,44.45 v58.17,45.21 57.66,44.96 55.63,42.93 v41.53,42.93 | v56.13,50.16 55.12,49.15 C103.1 | v54.1,55.24 54.1,54.23 R103.1 | v55.37,56.52 55.12,56.52 55.12,57.53 R107.2 | IC1.40 15.88,24.51 15.62,24.77 2.54,24.77 1.02,26.29 1.02,27.56 v41.15,27.56 45.09,27.56 48.39,30.86 87.63,30.86 88.77,29.72 88.77,28.7 87.5,27.43 SV4.4
  Bottom 0.254: 58.17,44.45 58.29,44.45 58.36,44.39

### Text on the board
tPlace: FreeCharge- | Controller.org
